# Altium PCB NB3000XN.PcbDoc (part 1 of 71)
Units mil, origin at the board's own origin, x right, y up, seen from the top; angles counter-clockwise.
Board outline 9527.56 x 6929.77 mil, 6 copper layers (Top Layer, GND+SHIELD, MidLayer1, MidLayer2, P2 - 3V3+5V0, Bottom Layer), stack 62.375 mil thick; 832 components, 1027 nets, 4655 pads, 4981 vias.
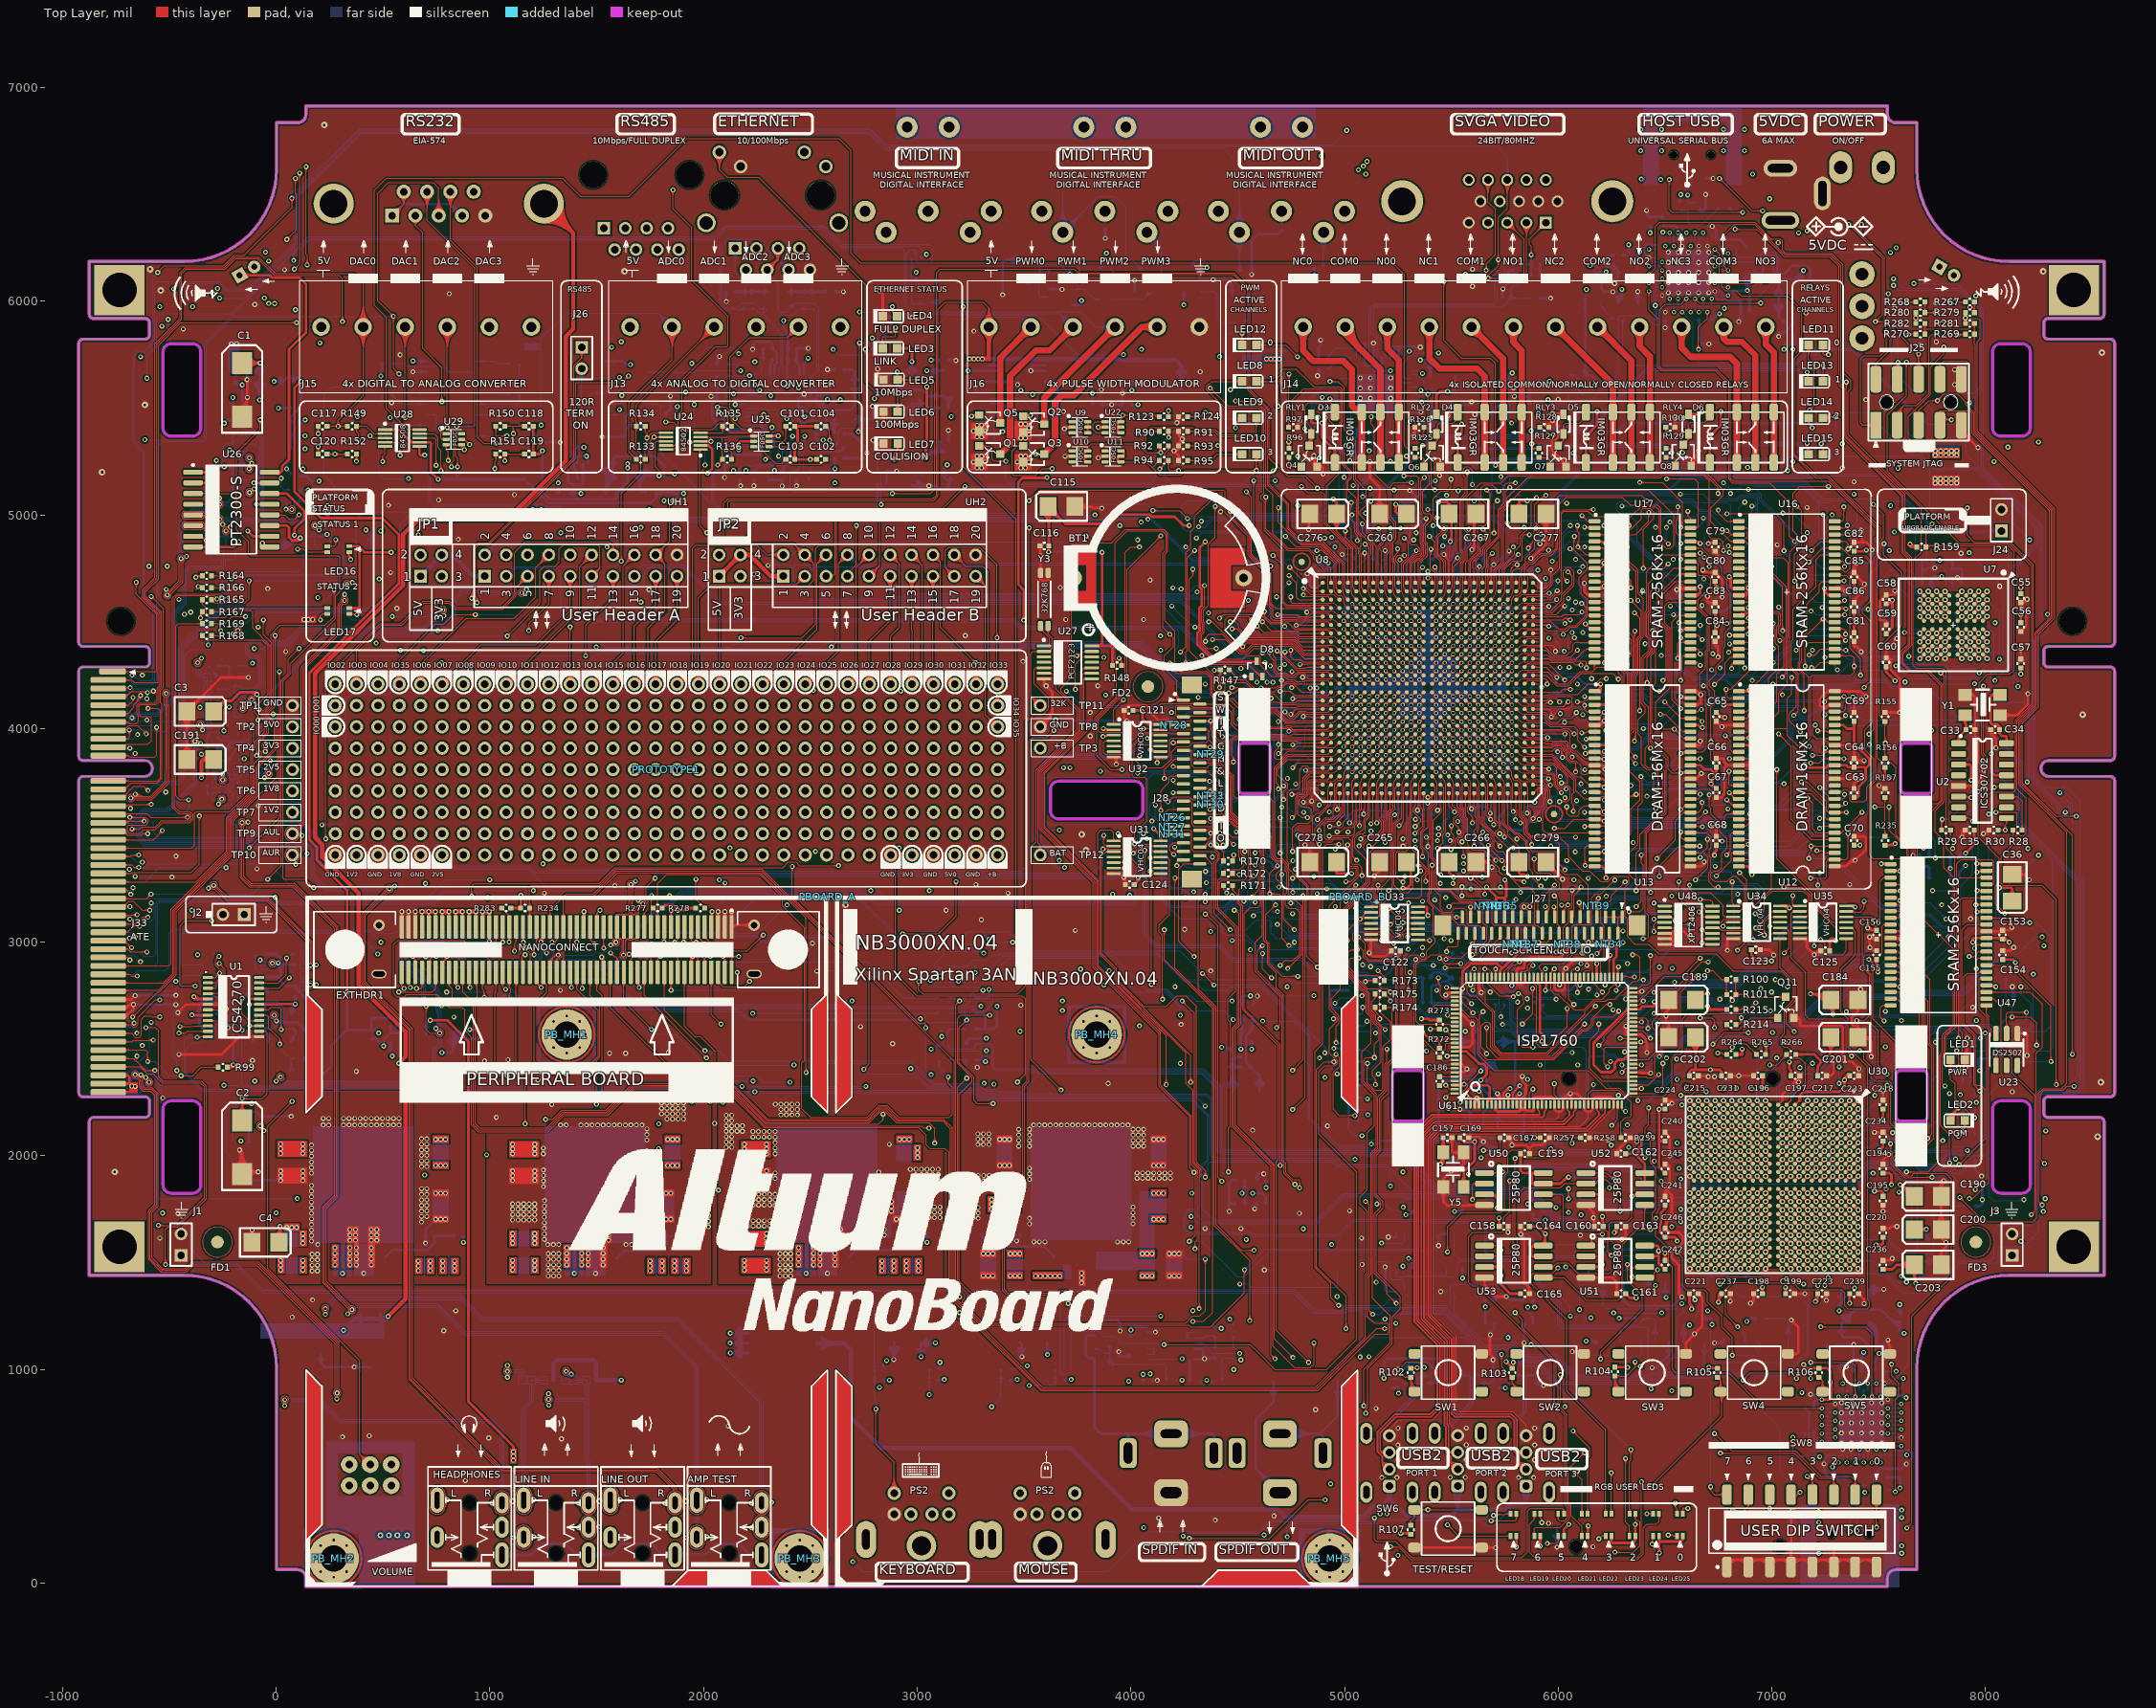
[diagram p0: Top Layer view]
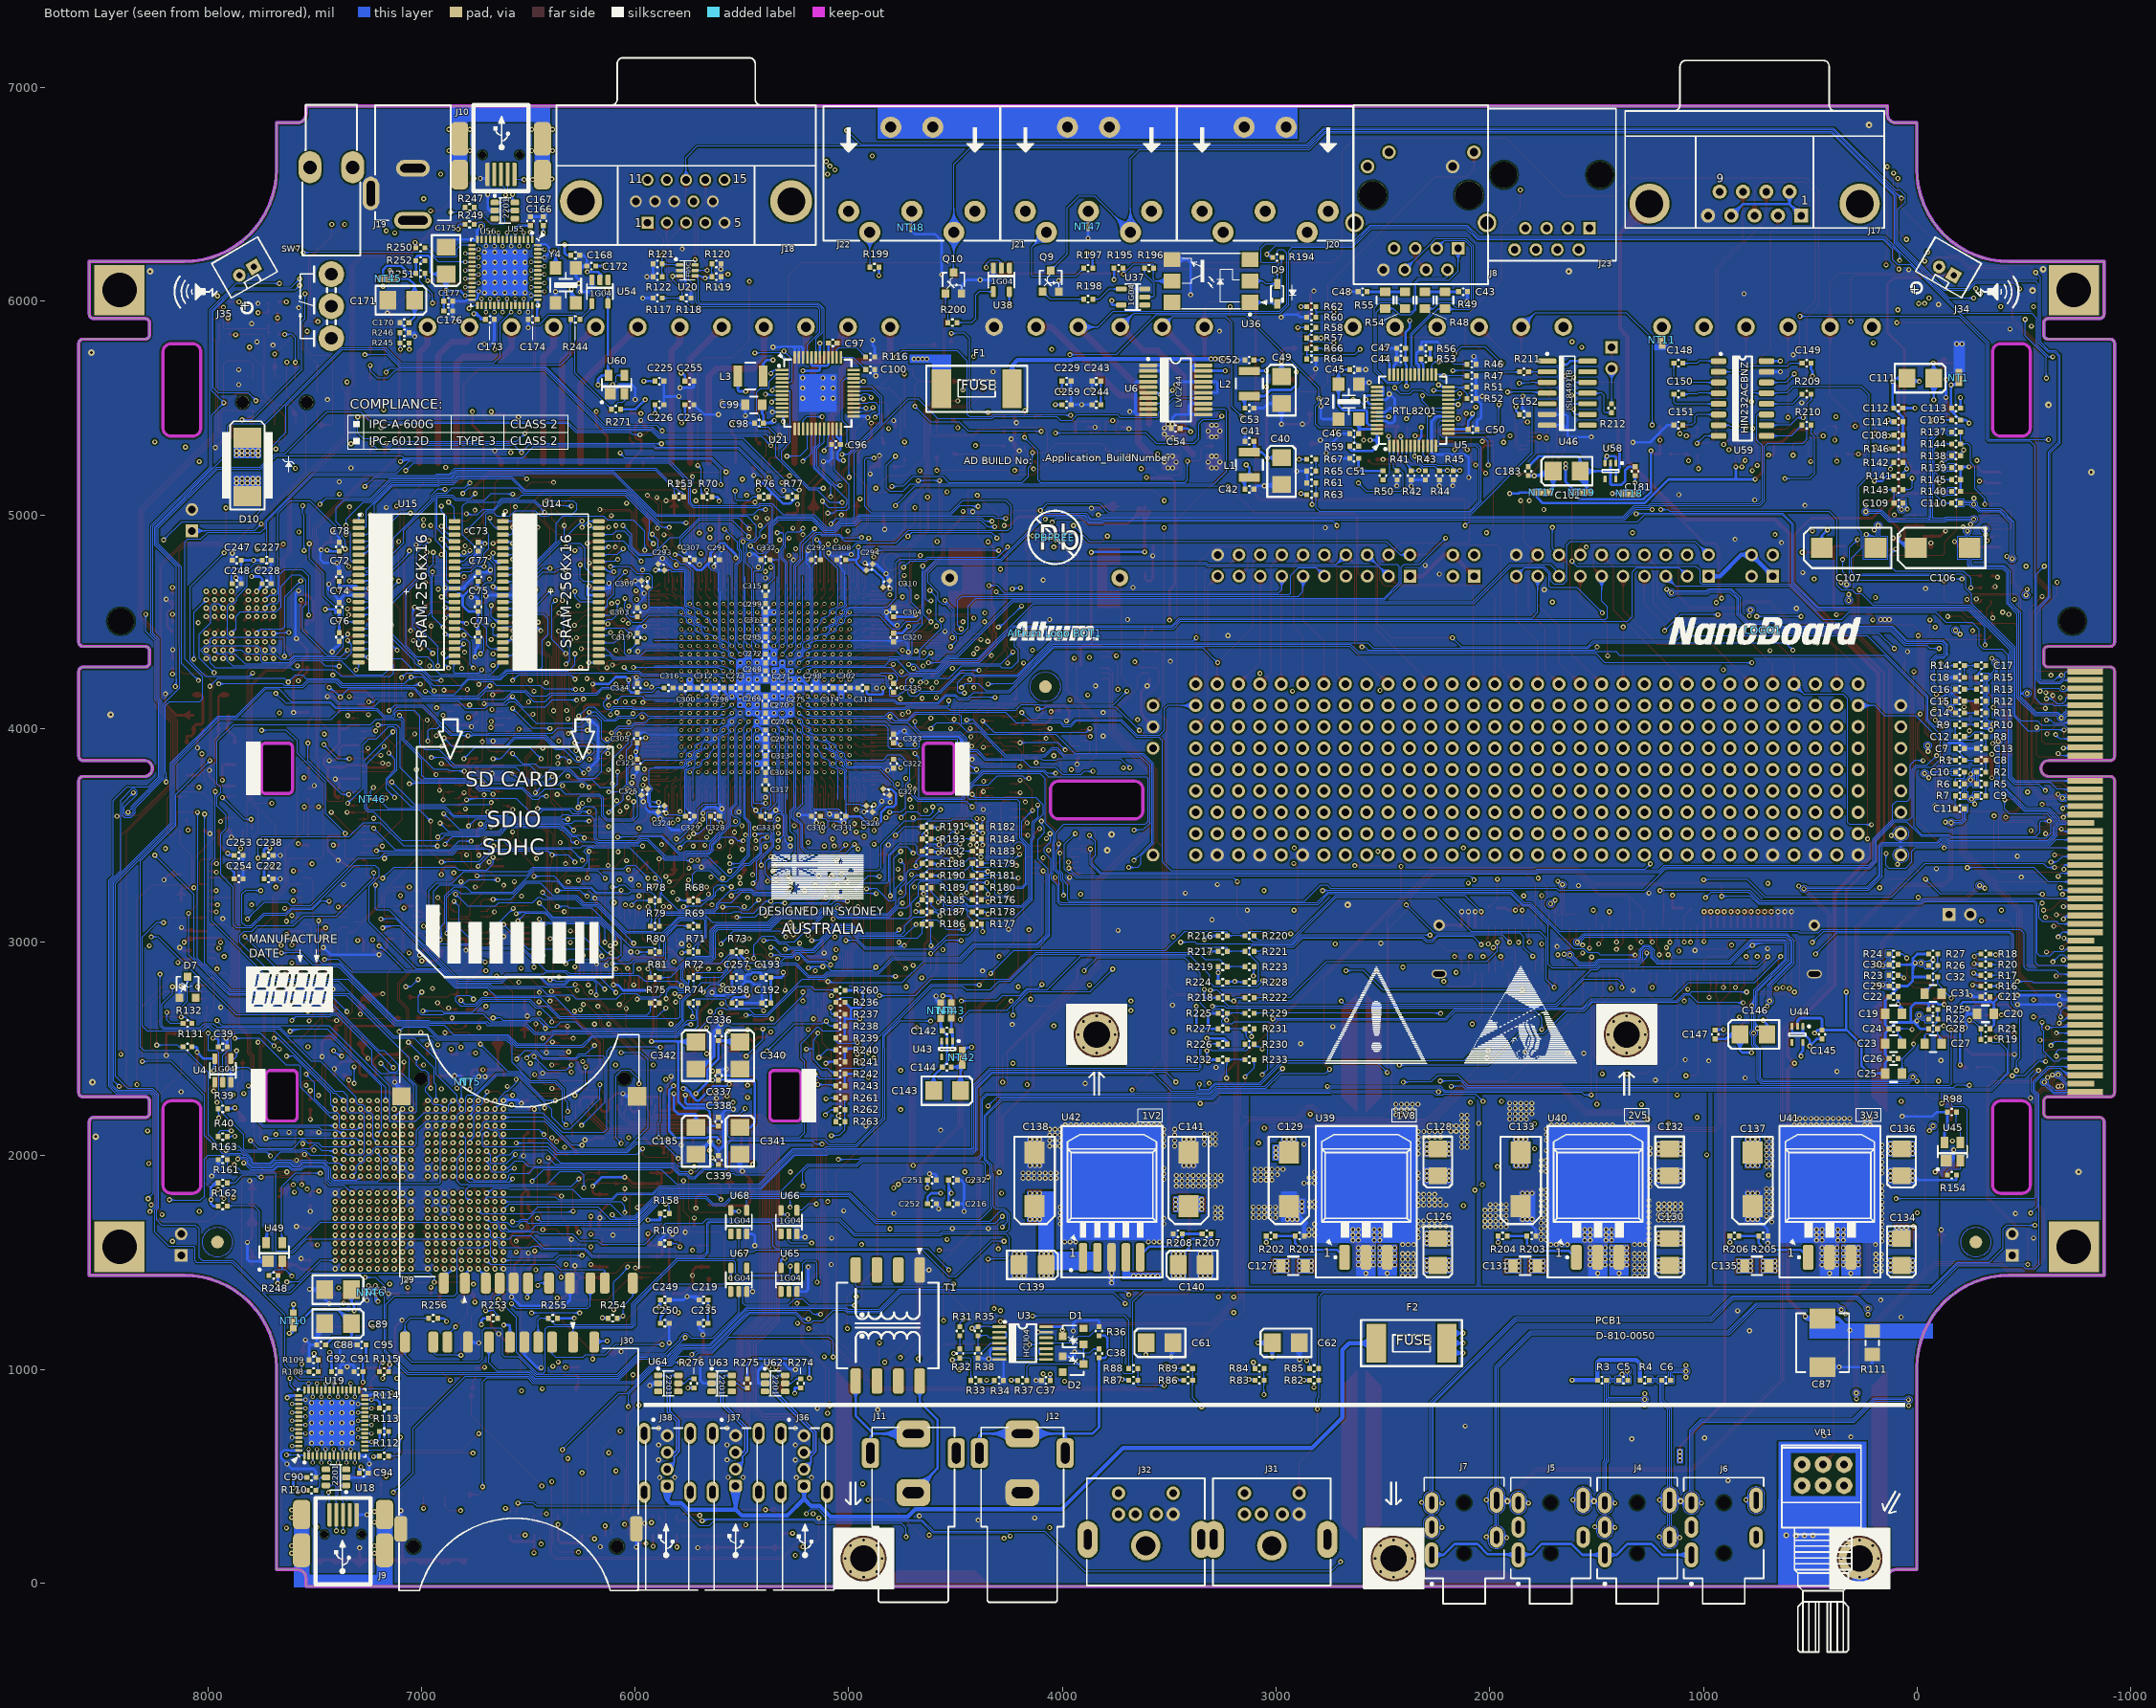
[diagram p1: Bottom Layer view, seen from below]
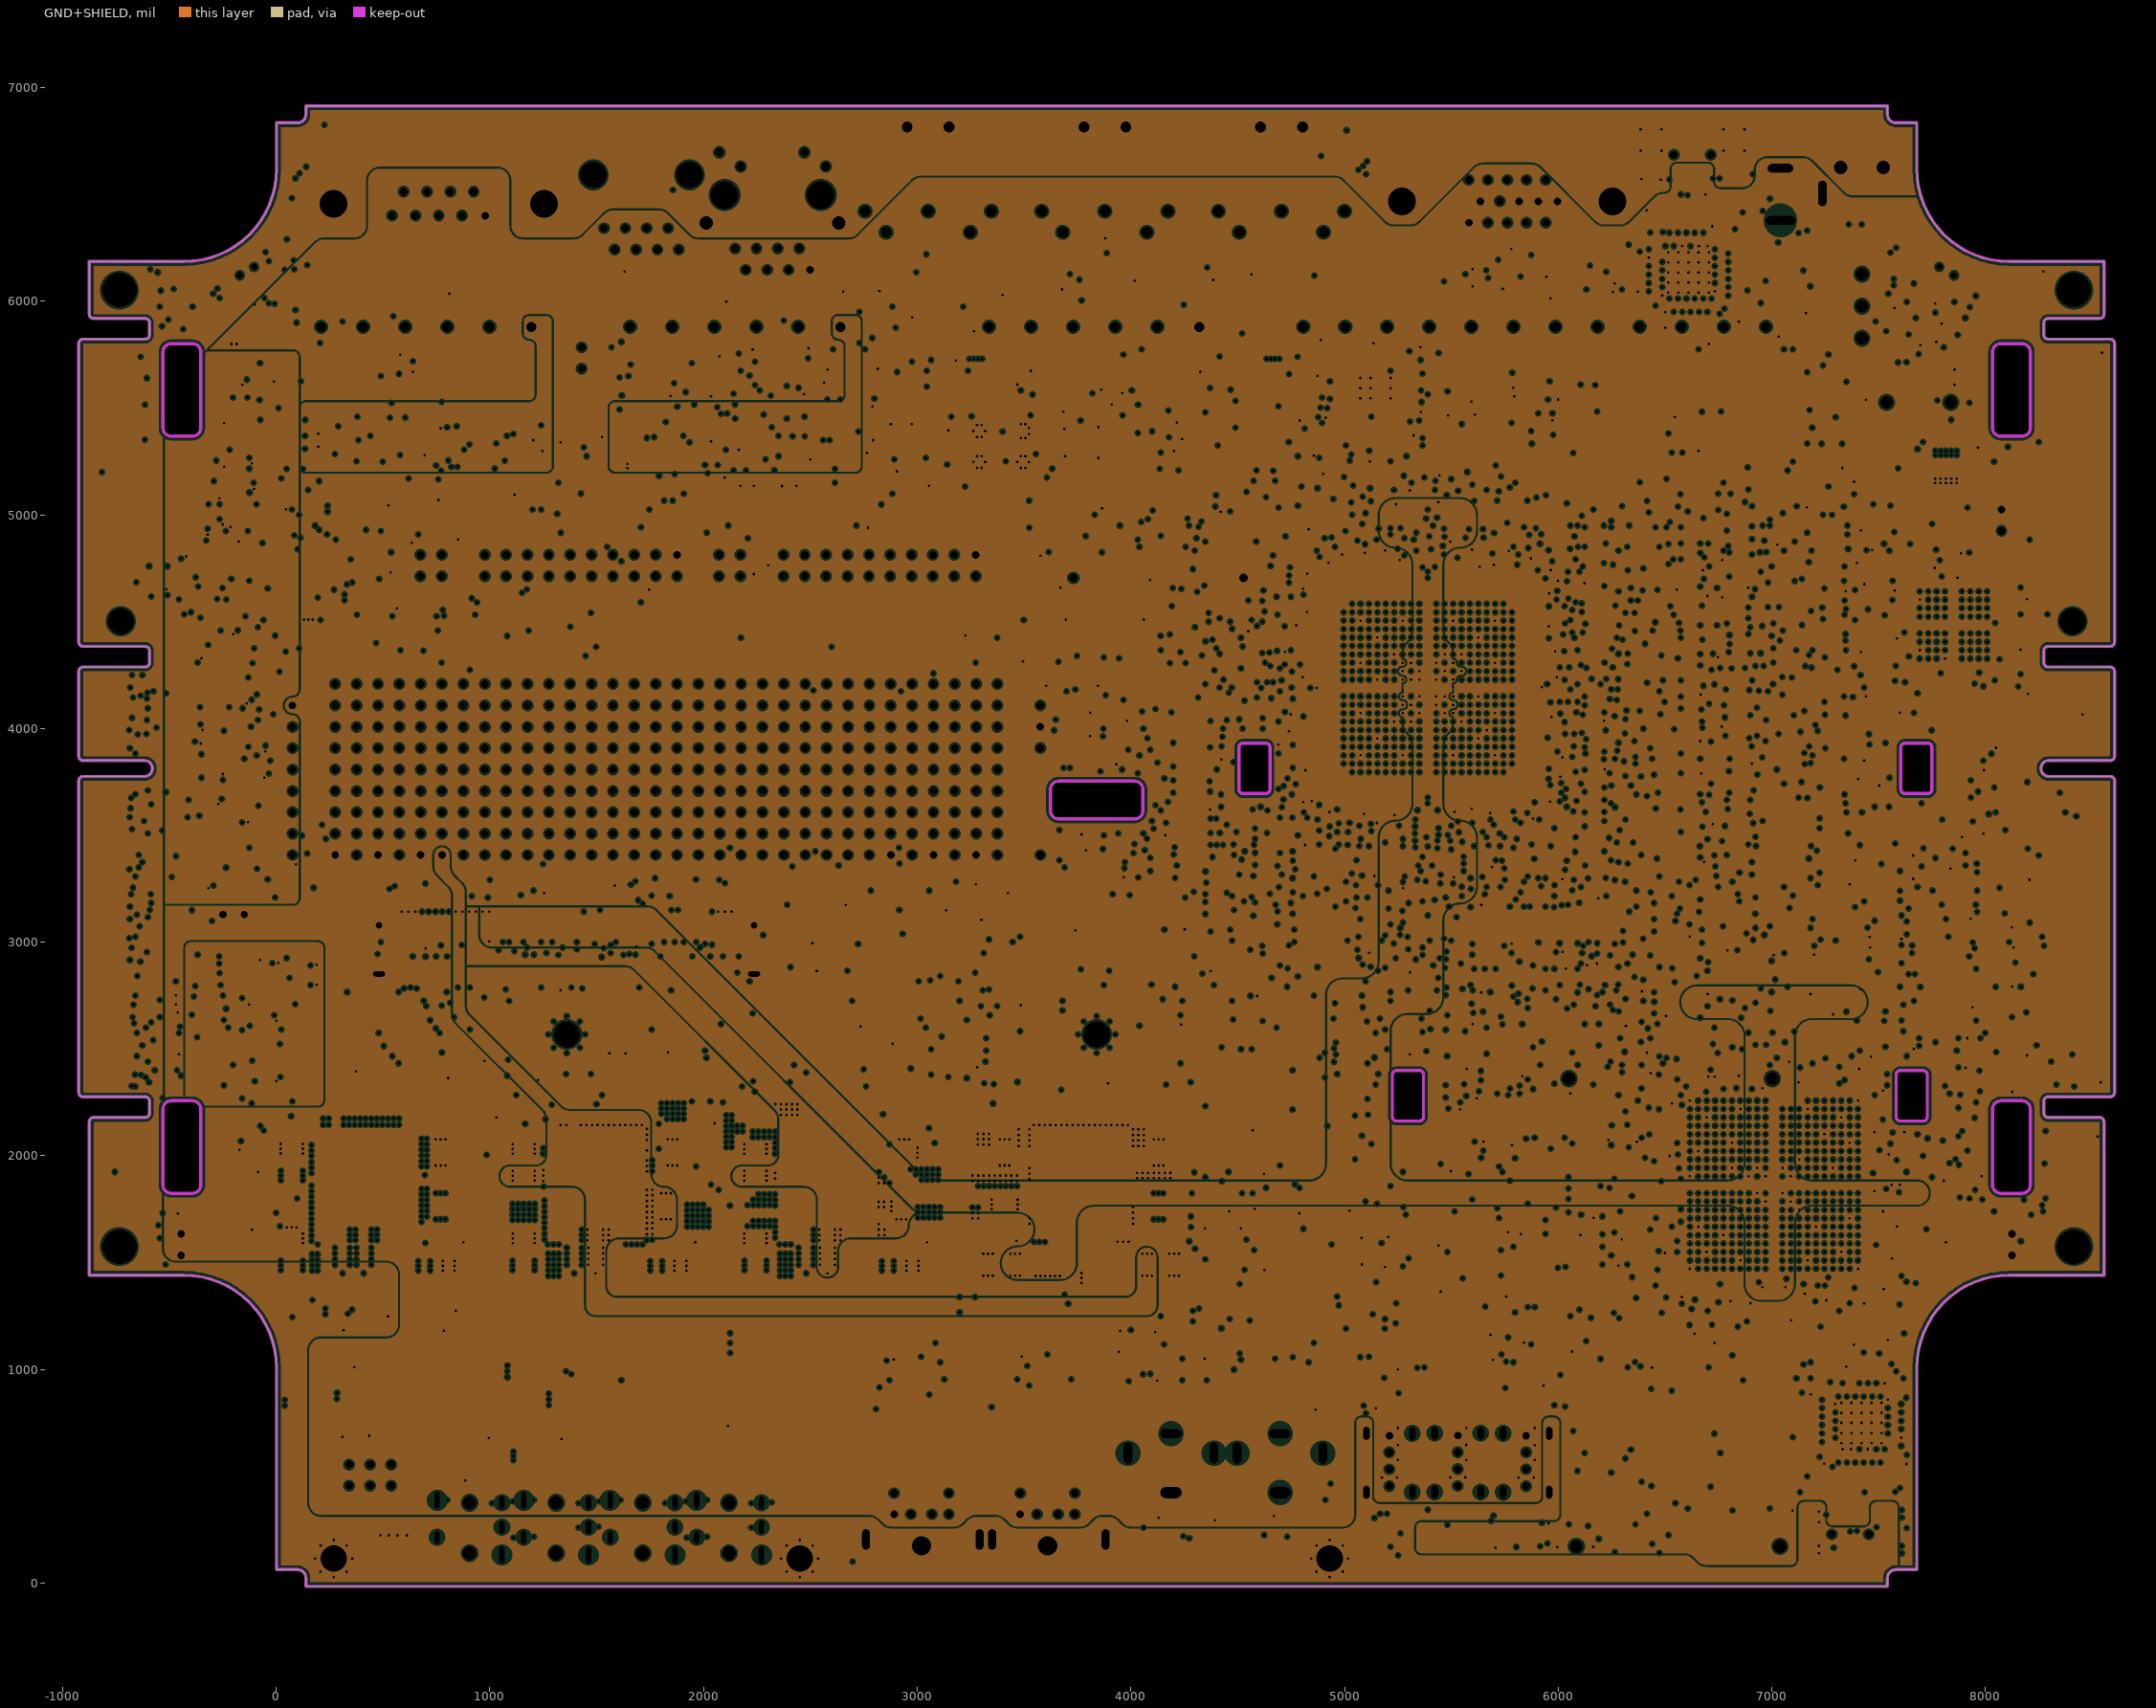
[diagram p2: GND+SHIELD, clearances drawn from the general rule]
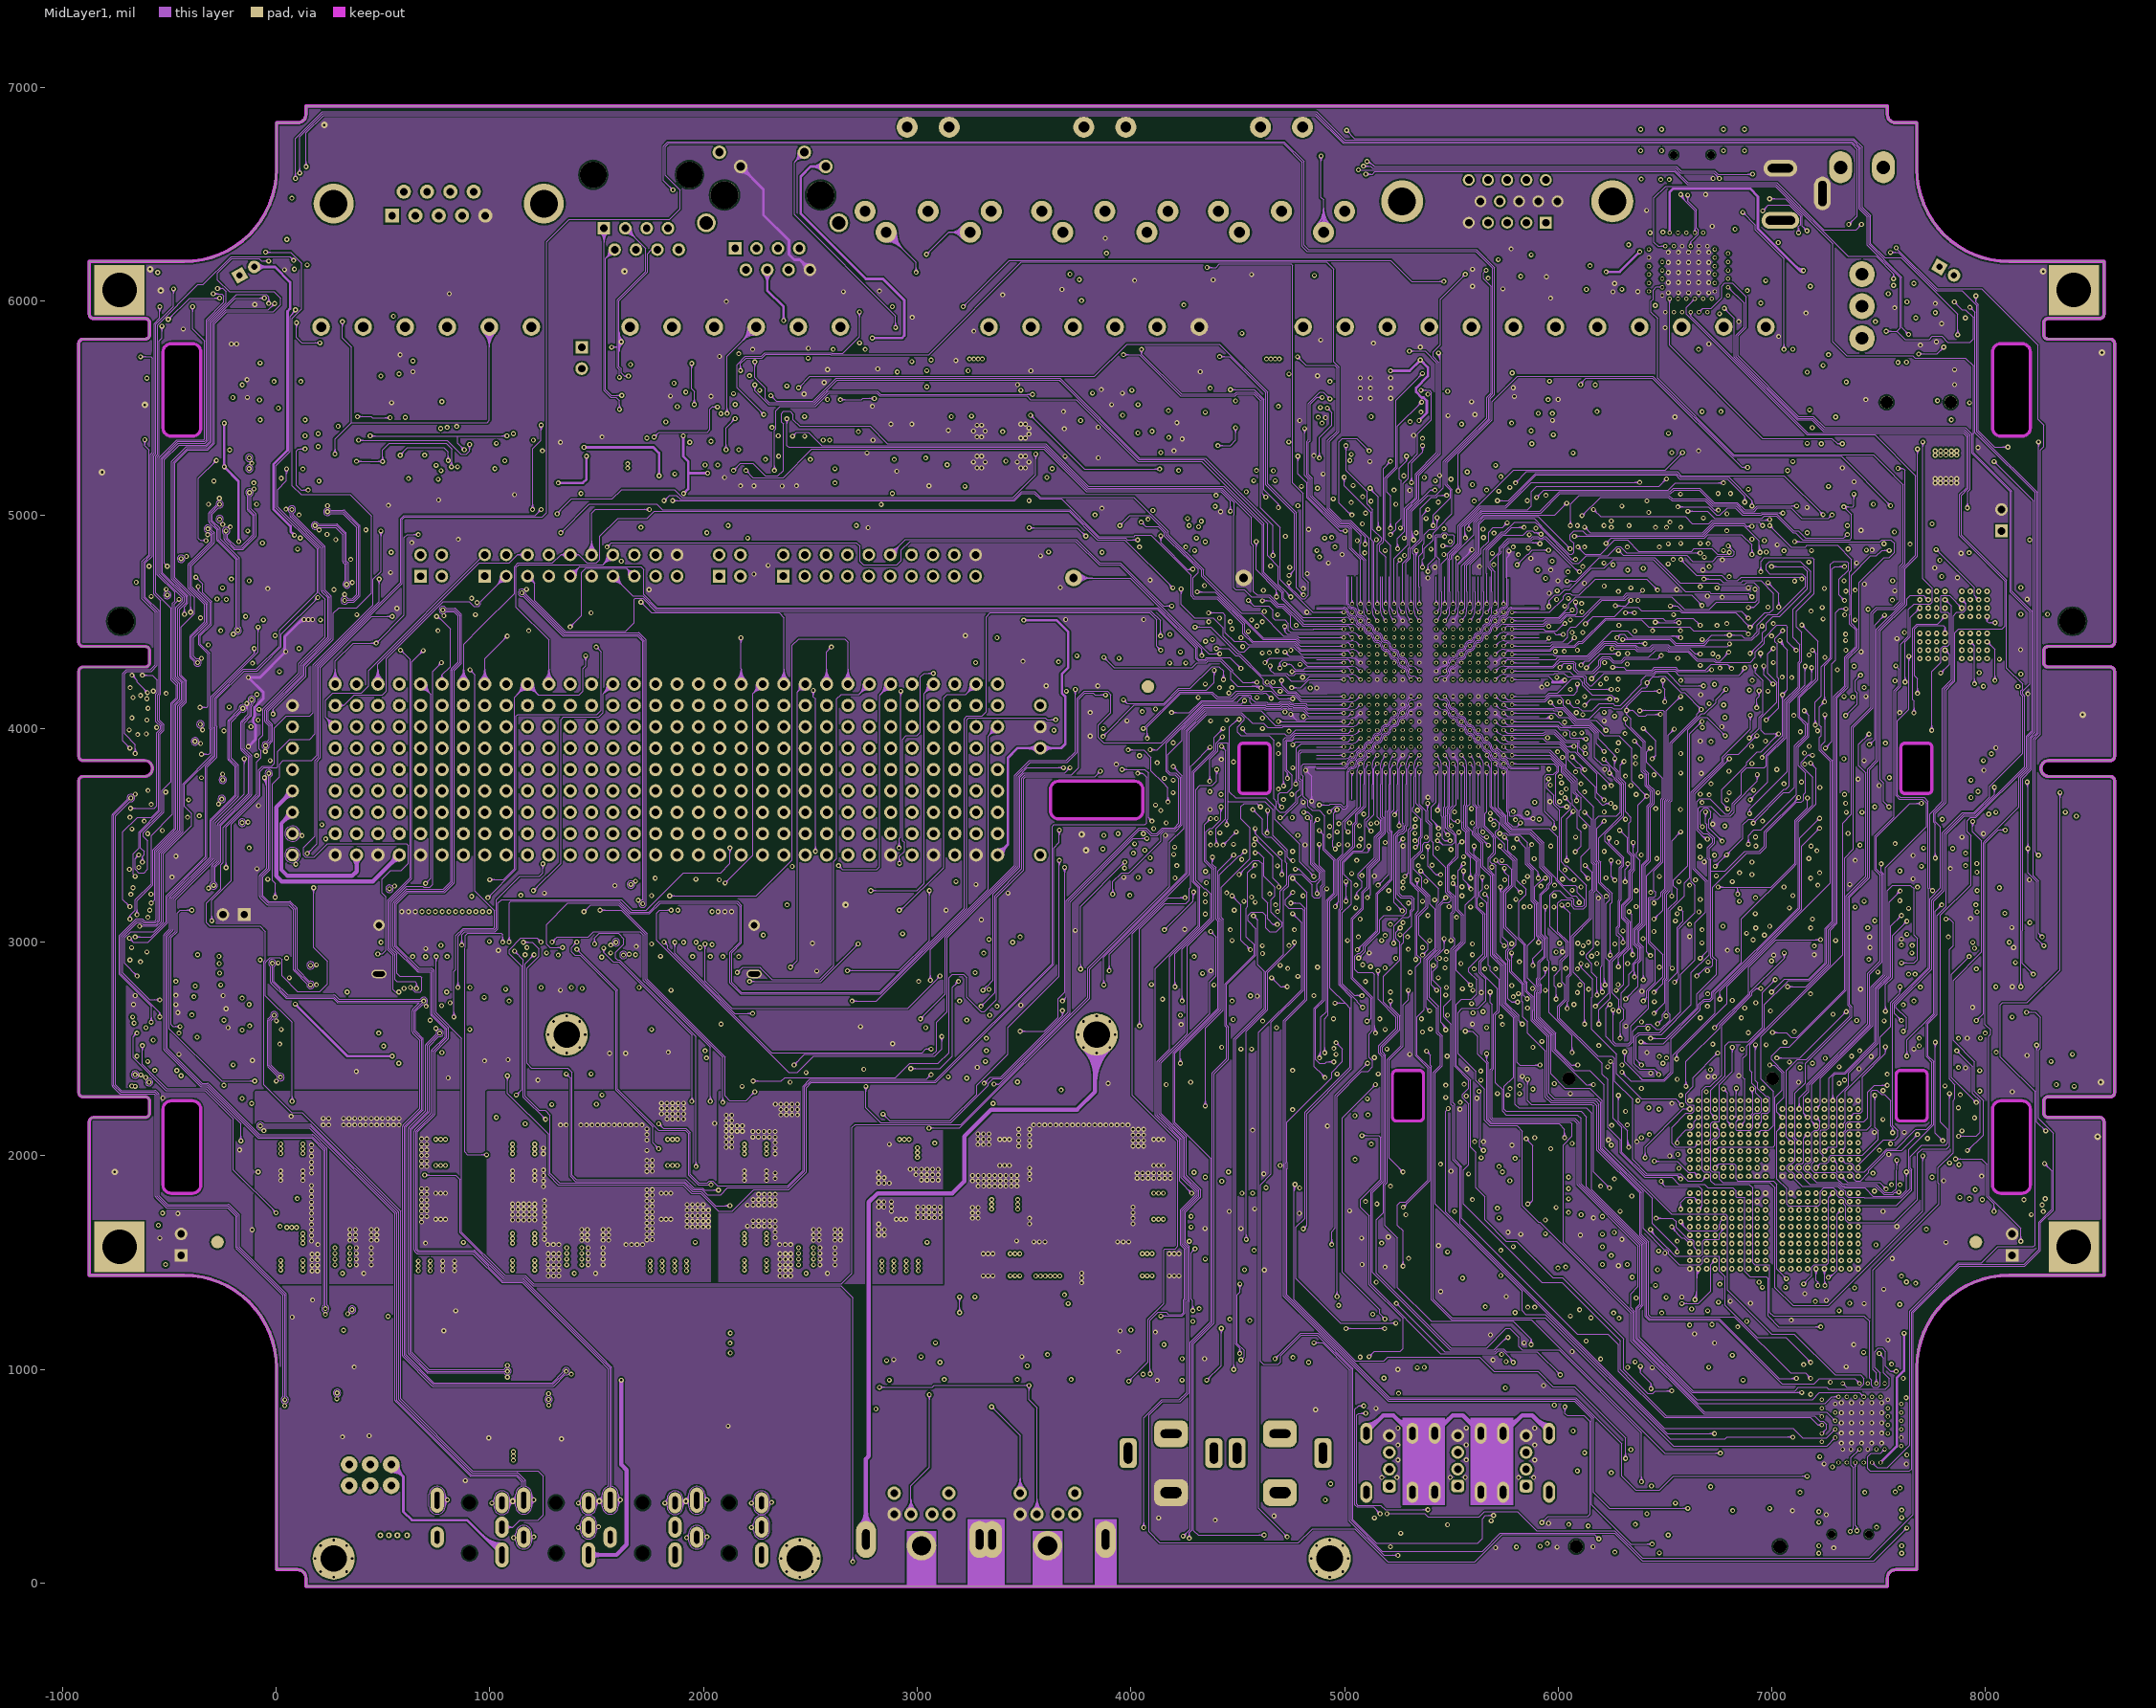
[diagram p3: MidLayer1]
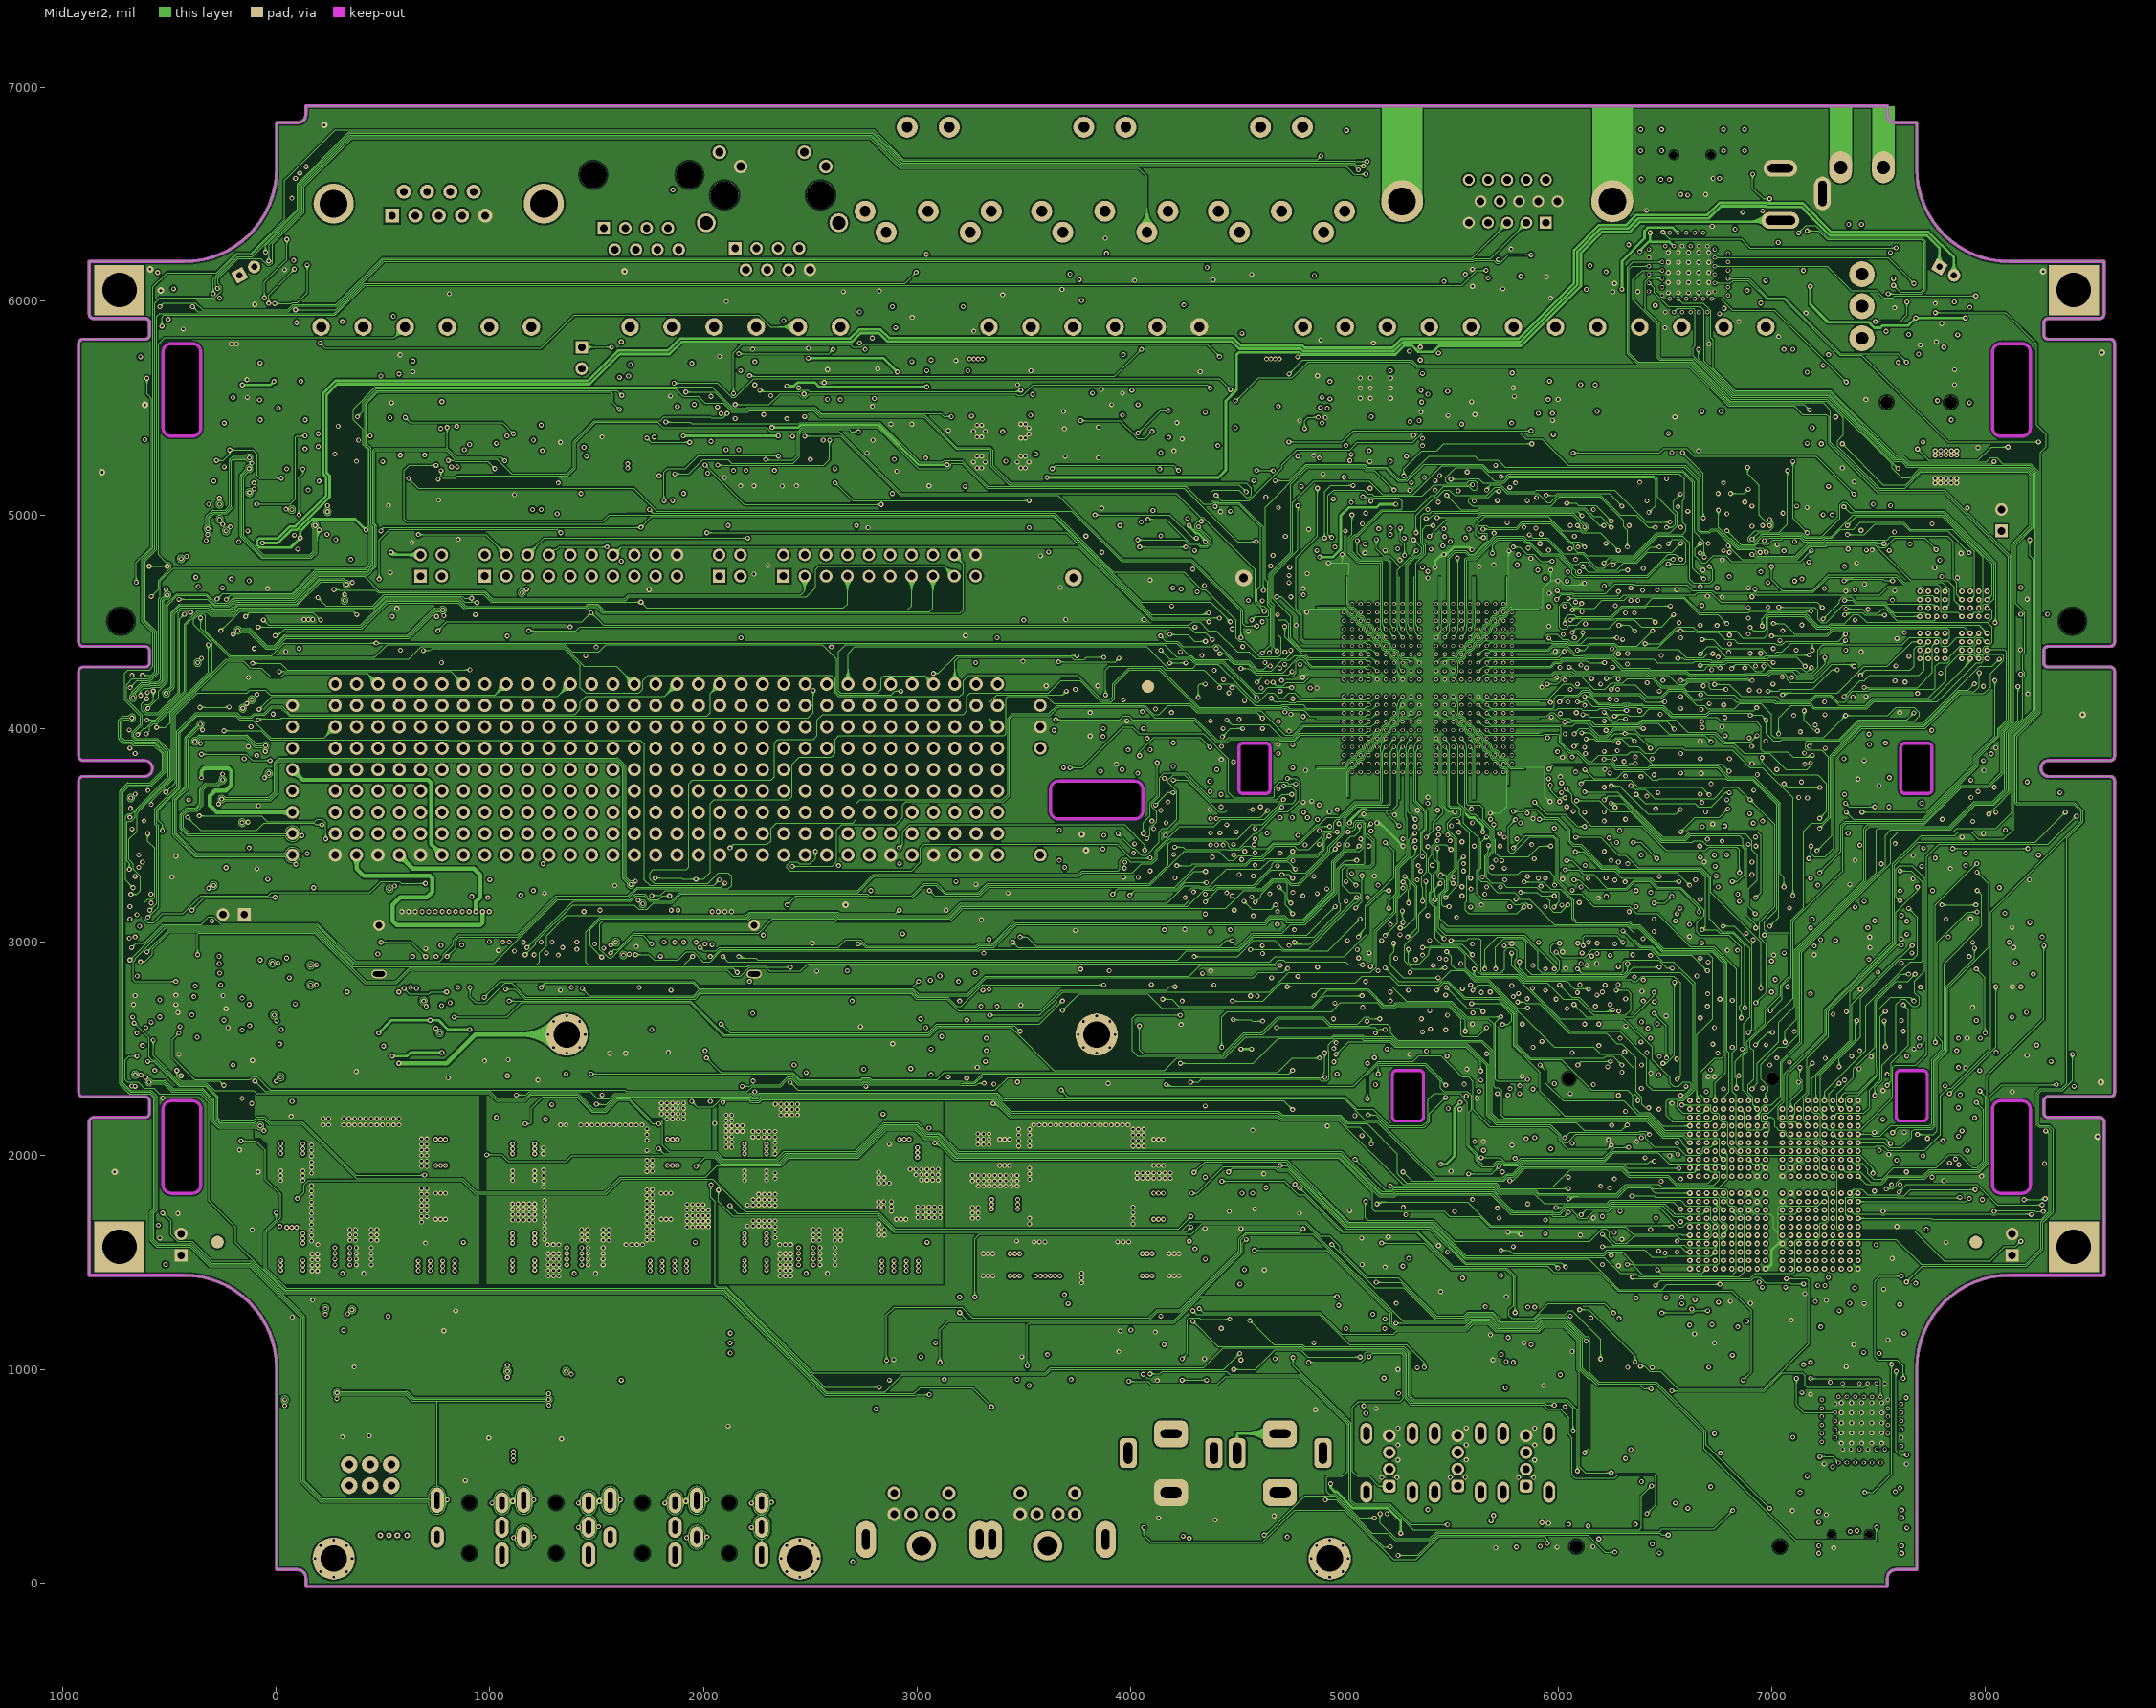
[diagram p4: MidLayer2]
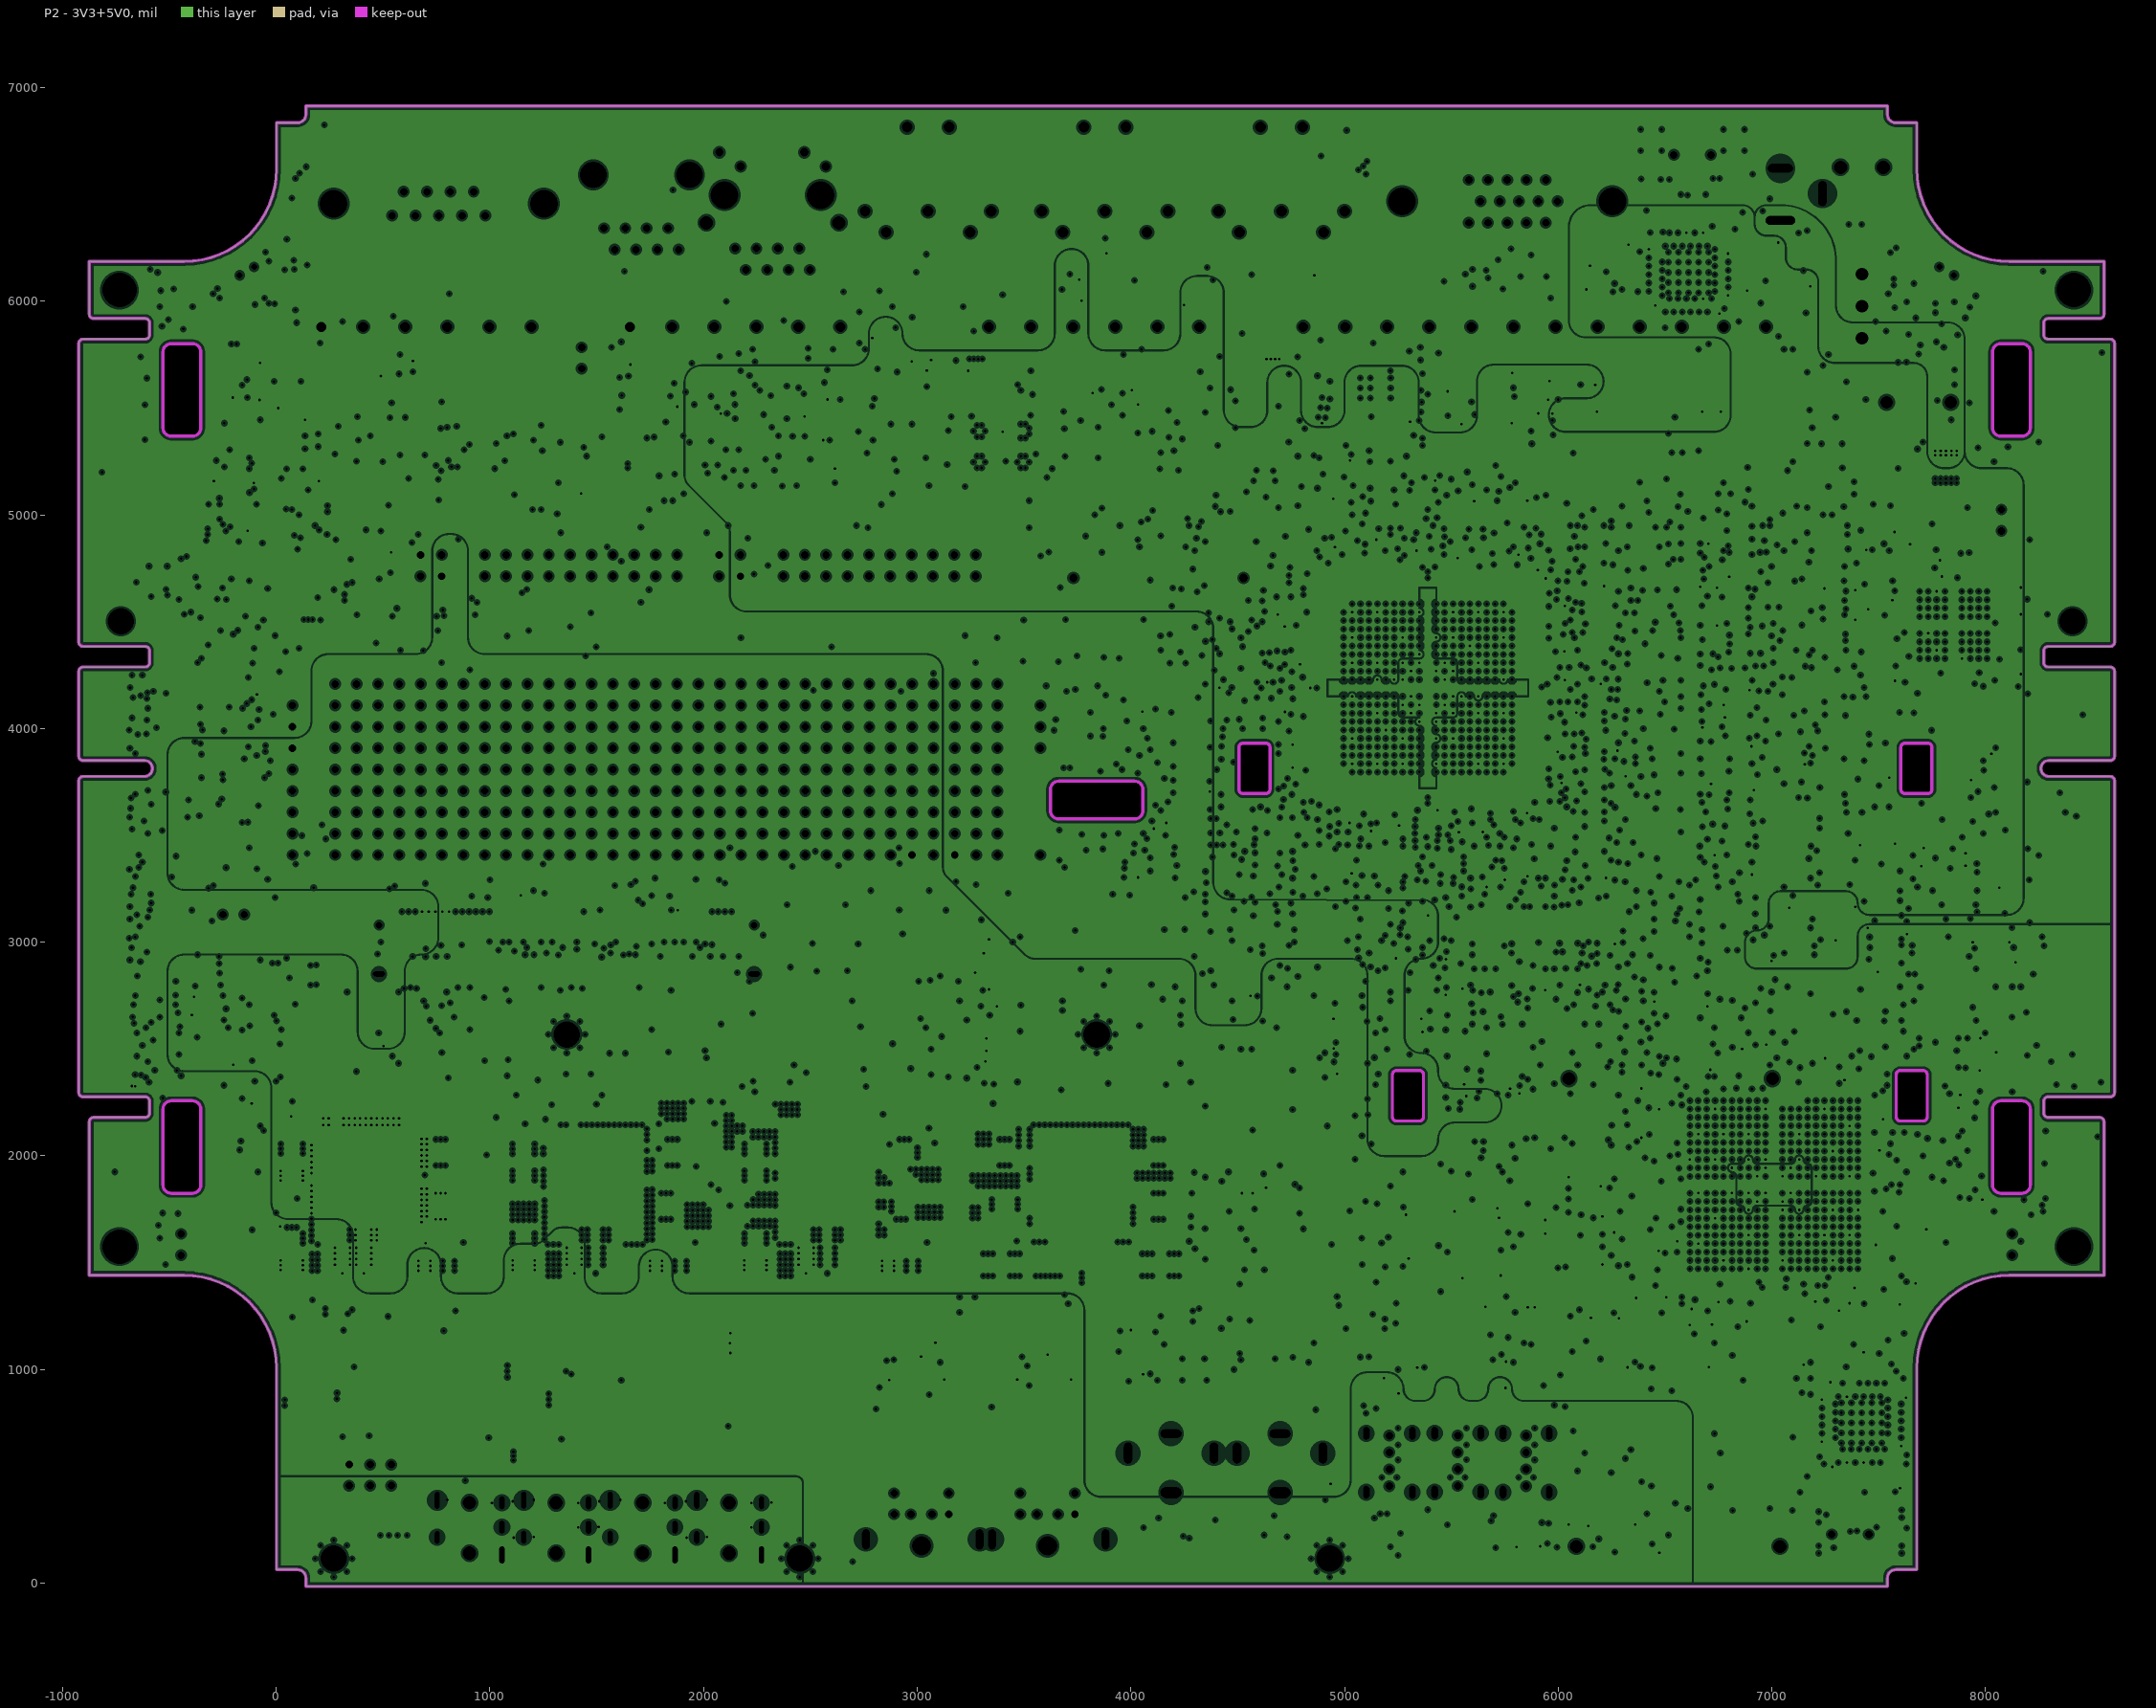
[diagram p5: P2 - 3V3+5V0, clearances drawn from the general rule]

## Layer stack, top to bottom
Top Layer: signal copper 1.4
Dielectric: core 7.874, FR-4, Dk 4.8
GND+SHIELD: plane copper 1.4173, net (Multiple Nets)
Dielectric: prepreg 12.9921, FR-4, Dk 4.8
MidLayer1: signal copper 1.4
Dielectric: core 7.874, FR-4, Dk 4.8
MidLayer2: signal copper 1.4
Dielectric: prepreg 12.6, FR-4, Dk 4.8
P2 - 3V3+5V0: plane copper 1.4173, net (Multiple Nets)
Dielectric: core 12.6, FR-4, Dk 4.8
Bottom Layer: signal copper 1.4

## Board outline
369 vertices, not listed, extent -923.8,-15.55 8603.76,6914.22
cut-out: 8170.69,2257.89 8179.45,2256.91 8187.77,2254 8195.24,2249.3 8201.47,2243.07 8206.16,2235.6 8209.07,2227.28 8210.06,2218.52 8210.06,1864.15 8209.07,1855.39 8206.16,1847.06 8201.47,1839.6 8195.24,1833.36 8187.77,1828.67 8179.45,1825.76 8170.69,1824.77 8072.26,1824.77 8063.5,1825.76 8055.18,1828.67 8047.72,1833.36 8041.48,1839.6 8036.79,1847.06 8033.88,1855.39 8032.89,1864.15 8032.89,2218.52 8033.88,2227.28 8036.79,2235.6 8041.48,2243.07 8047.72,2249.3 8055.18,2254 8063.5,2256.91 8072.26,2257.89
cut-out: 7707.86,2163.13 7601.56,2163.13 7597.18,2163.62 7593.02,2165.08 7589.29,2167.42 7586.17,2170.54 7583.83,2174.27 7582.37,2178.43 7581.87,2182.81 7581.87,2379.69 7582.37,2384.07 7583.83,2388.23 7586.17,2391.96 7589.29,2395.08 7593.02,2397.42 7597.18,2398.88 7601.56,2399.37 7707.86,2399.37 7712.24,2398.88 7716.4,2397.42 7720.13,2395.08 7723.25,2391.96 7725.6,2388.23 7727.05,2384.07 7727.54,2379.69 7727.54,2182.81 7727.05,2178.43 7725.6,2174.27 7723.25,2170.54 7720.13,2167.42 7716.4,2165.08 7712.24,2163.62
cut-out: 3623.45,3714.76 3624.43,3723.52 3627.34,3731.84 3632.03,3739.31 3638.27,3745.54 3645.73,3750.24 3654.05,3753.15 3662.81,3754.13 4017.15,3754.13 4025.91,3753.15 4034.23,3750.24 4041.69,3745.54 4047.93,3739.31 4052.62,3731.84 4055.53,3723.52 4056.52,3714.76 4056.52,3616.32 4055.53,3607.56 4052.62,3599.24 4047.93,3591.77 4041.69,3585.54 4034.23,3580.85 4025.91,3577.94 4017.15,3576.95 3662.81,3576.95 3654.05,3577.94 3645.73,3580.85 3638.27,3585.54 3632.03,3591.77 3627.34,3599.24 3624.43,3607.56 3623.45,3616.32
cut-out: -490.73,5368.5 -499.49,5369.49 -507.81,5372.4 -515.27,5377.09 -521.51,5383.32 -526.2,5390.79 -529.11,5399.11 -530.1,5407.88 -530.1,5762.25 -529.11,5771.01 -526.2,5779.33 -521.51,5786.8 -515.27,5793.03 -507.81,5797.72 -499.49,5800.64 -490.73,5801.62 -392.3,5801.62 -383.54,5800.64 -375.22,5797.72 -367.76,5793.03 -361.52,5786.8 -356.83,5779.33 -353.92,5771.01 -352.93,5762.25 -352.93,5407.88 -353.92,5399.11 -356.83,5390.79 -361.52,5383.32 -367.76,5377.09 -375.22,5372.4 -383.54,5369.49 -392.3,5368.5
cut-out: 8210.06,5762.25 8210.06,5407.88 8209.07,5399.11 8206.16,5390.79 8201.47,5383.32 8195.24,5377.09 8187.77,5372.4 8179.45,5369.49 8170.69,5368.5 8072.26,5368.5 8063.5,5369.49 8055.18,5372.4 8047.72,5377.09 8041.48,5383.32 8036.79,5390.79 8033.88,5399.11 8032.89,5407.88 8032.89,5762.25 8033.88,5771.01 8036.79,5779.33 8041.48,5786.8 8047.72,5793.03 8055.18,5797.72 8063.5,5800.64 8072.26,5801.62 8170.69,5801.62 8179.45,5800.64 8187.77,5797.72 8195.24,5793.03 8201.47,5786.8 8206.16,5779.33 8209.07,5771.01
cut-out: -530.1,1864.15 -530.1,2218.52 -529.11,2227.28 -526.2,2235.6 -521.51,2243.07 -515.27,2249.3 -507.81,2253.99 -499.49,2256.91 -490.73,2257.89 -392.3,2257.89 -383.54,2256.91 -375.22,2253.99 -367.76,2249.3 -361.52,2243.07 -356.83,2235.6 -353.92,2227.28 -352.93,2218.52 -352.93,1864.15 -353.92,1855.38 -356.83,1847.06 -361.52,1839.6 -367.76,1833.36 -375.22,1828.67 -383.54,1825.76 -392.3,1824.77 -490.73,1824.77 -499.49,1825.76 -507.81,1828.67 -515.27,1833.36 -521.51,1839.6 -526.2,1847.06 -529.11,1855.38
cut-out: 5243.76,2399.37 5350.06,2399.37 5354.43,2398.88 5358.6,2397.42 5362.33,2395.08 5365.45,2391.96 5367.79,2388.23 5369.25,2384.07 5369.74,2379.69 5369.74,2182.81 5369.25,2178.43 5367.79,2174.27 5365.45,2170.54 5362.33,2167.42 5358.6,2165.08 5354.43,2163.62 5350.06,2163.13 5243.76,2163.13 5239.37,2163.62 5235.21,2165.08 5231.48,2167.42 5228.37,2170.54 5226.02,2174.27 5224.57,2178.43 5224.07,2182.81 5224.07,2379.69 5224.57,2384.07 5226.02,2388.23 5228.37,2391.96 5231.48,2395.08 5235.21,2397.42 5239.37,2398.88
cut-out: 4505.53,3912.08 4506.03,3916.47 4507.48,3920.63 4509.83,3924.36 4512.95,3927.48 4516.68,3929.82 4520.84,3931.28 4525.22,3931.77 4631.52,3931.77 4635.9,3931.28 4640.06,3929.82 4643.79,3927.48 4646.91,3924.36 4649.25,3920.63 4650.71,3916.47 4651.21,3912.08 4651.21,3715.21 4650.71,3710.83 4649.25,3706.67 4646.91,3702.94 4643.79,3699.82 4640.06,3697.47 4635.9,3696.02 4631.52,3695.52 4525.22,3695.52 4520.84,3696.02 4516.68,3697.47 4512.95,3699.82 4509.83,3702.94 4507.48,3706.67 4506.03,3710.83 4505.53,3715.21
cut-out: 7623.64,3931.77 7729.94,3931.77 7734.32,3931.28 7738.48,3929.82 7742.21,3927.48 7745.33,3924.36 7747.67,3920.63 7749.13,3916.47 7749.62,3912.08 7749.62,3715.21 7749.13,3710.83 7747.67,3706.67 7745.33,3702.94 7742.21,3699.82 7738.48,3697.47 7734.32,3696.02 7729.94,3695.52 7623.64,3695.52 7619.26,3696.02 7615.1,3697.47 7611.37,3699.82 7608.25,3702.94 7605.9,3706.67 7604.45,3710.83 7603.95,3715.21 7603.95,3912.08 7604.45,3916.47 7605.9,3920.63 7608.25,3924.36 7611.37,3927.48 7615.1,3929.82 7619.26,3931.28

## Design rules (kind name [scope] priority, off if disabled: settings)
Clearance Polygons [InPolygon] p1: gap=8
Clearance "General Clearance" [All] p2: gap=4
ComponentClearance "Small SMD" [HasFootprint('RESC1005-STAR') or Hasfootprint('CAPC3528-STAR') or Hasfootprint('0603LED')   or Hasfootprint('CAPC1005-STAR')] p1: gap=-39.37 collisioncheckmode=3 verticalgap=10 showdistances=FALSE
ComponentClearance "Peripheral and Daughter" [InComponentClass('Plug In Boards') vs InComponentClass('Plug In Board Headers') or HasFootprint('STANDOFF_SOLDER_3MM')] p2: gap=0 collisioncheckmode=3 verticalgap=0 showdistances=FALSE
ComponentClearance "Net Ties" [IsNetTieComponent] p3: gap=-39.37 collisioncheckmode=3 verticalgap=-39.37 showdistances=FALSE
ComponentClearance [All] p4: gap=7.87 collisioncheckmode=3 verticalgap=39.37 showdistances=FALSE
DiffPairsRouting DiffPair_DiffPairsRouting [All] p1: maxlimit=12.6 minlimit=11.02 mostfreqgap=11.81 maxuncoupledlength=500
DiffPairsRouting PairRoute [All] p2: maxlimit=5.91 minlimit=5 mostfreqgap=5 maxuncoupledlength=393.7
FabricationTestPointUsage TestPointUsage [All] p1 off: valid=0 allowmultiple=FALSE
FabricationTestpoint Testpoint [All] p1 off: side=3 testpointundercomponent=TRUE minsize=40 maxsize=100 preferedsize=60 minholesize=0 maxholesize=40 preferedholesize=32 testpointgrid=1 allowsidetop=TRUE allowsidebottom=TRUE usegrid=TRUE gridtolerance=0.01
FanoutControl Fanout_BGA [All] p1: bgadir=Out bgaviamode=Centered fanoutstyle=BGA fanoutdirection=OutOnly viagrid=1 // Fanout_BGA (Default Rule)
FanoutControl Fanout_Default [All] p5: bgadir=Out bgaviamode=Centered fanoutstyle=BGA fanoutdirection=Alternating viagrid=1 // Fanout_Default (Default Rule)
HoleSize [IsPad And (holesize <> 0)] p1: absolutevalues=TRUE maxlimit=204.72 minlimit=11.81 maxpercent=80.000 minpercent=20.000
MatchedLengths DiffPair_MatchedLengths [(IsDifferentialPair And (Name = 'USB_DP'))] p1: tolerance=393.7 checknetsindiffpair=TRUE checkdiffpairvsdiffpair=TRUE checkothers=TRUE
MatchedLengths DiffPair_MatchedLengths_1 [(IsDifferentialPair And (Name = 'DIFF_RX1'))] p2: tolerance=1000 checknetsindiffpair=TRUE checkdiffpairvsdiffpair=TRUE checkothers=TRUE
MinimumAnnularRing [PadIsPlated And (Name <> 'Y1_RT')] p1 off: minimumring=7.87
PlaneClearance [All] p1: clearance=10
PlaneConnect [All] p1: planeconnectstyle=Direct reliefexpansion=20 reliefentries=4 reliefconductorwidth=10 reliefairgap=10
PolygonConnect [All] p1: connectstyle=Direct reliefconductorwidth=10 reliefentries=4 polygonreliefangle="90 Angle"
RoutingVias [All] p1: holewidth=11.81 width=23.62 viastyle="Through Hole" minholewidth=11.81 minwidth=23 maxholewidth=39.37 maxwidth=78.74
ShortCircuit ShortCircuit_1 [Net = 'No Net' vs Net = 'No Net'] p1: allowed=TRUE
ShortCircuit [All] p2: allowed=FALSE
SilkscreenOverComponentPads [All] p1: minsilkscreentomaskgap=10
SolderMaskExpansion SolderMaskExpansion_Vias [IsVia] p1: expansion=-30
SolderMaskExpansion [All] p2: expansion=1.5
Width [All] p1: maxlimit=157.48 minlimit=4 preferedwidth=5
17 further rules are at their usual default settings.

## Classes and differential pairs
channel class FPGA_Bypass_3V3: DECOUPLING_CAPS_3V31 DECOUPLING_CAPS_3V32
channel class FPGA_Bypass_1V2: DECOUPLING_CAPS_1V21 DECOUPLING_CAPS_1V22
channel class USB_CY7C68001-56LFC: DBUSB_TXRX1 DBUSB_TXRX2
channel class PSU_ZXCL330_3V3: PSU_A3V3_ADC1 PSU_A3V3_ADC2 PSU_A3V3_CODEC PSU_A3V3_DAC
channel class PSU_1084_ADJ: PSU_1V8 PSU_2V5 PSU_3V3
channel class LED_RGB_SMDx2: HOST_LED U_LED_01 U_LED_23 U_LED_45 U_LED_67
channel class CON_SD_KSDC012551: CON_DBSD1 CON_DBSD2
channel class SRAM_256Kx16_TSOP44: U_SRAM1 U_SRAM2
channel class RELAY_SMT_5V_IM03GR: U_RELAY0 U_RELAY1 U_RELAY2 U_RELAY3
pad class "GND Net Link Pads": NT1-2 NT2-1 NT2-2 U13-11
pad class Connector_Slot_Pads: J6-1 J6-3 J7-1 J7-2 J7-3 U1MIC-6
polygon class HeatsinkPolygons: POWER-BL-1V2 POWER-BL-1V8 POWER-BL-2V5 POWER-BL-3V3 POWER-BL-VCCX POWER-TL-1V2 POWER-TL-1V8 POWER-TL-2V5 POWER-TL-3V3 POWER-TL-VCCX
channel class PC_PS2: KEYBOARD MOUSE
component class StatusLEDS: C39 LED1 LED2 R39 R40 U4
channel class PWRCTRL_RELAY_PWM_28V2A: PWRPWM0 PWRPWM1 PWRPWM2 PWRPWM3
channel class CON_PS2PORT_MINIDIN6F_BLACK: CON_KEYBOARD CON_MOUSE
channel class CON_MINI_USBB_RA_KME04-USBMU03A01-1: CON_DBUSB CON_USB
channel class FLASH_M25PX0_SPI_8Mbit: GOLDEN SYSBOOT
channel class CON_USBA_RA_UPRIGHT: CON_USB1 CON_USB2 CON_USB3
component class ADC: C101 C102 C103 C104 R133 R134 R135 R136 U24 U25
component class AMP_PT2300: C105 C106 C107 C108 C109 C110 C111 C112 C113 C114 R137 R138 R139 R140 R141 R142 R143 R144 R145 R146 U26
component class "ATE INTERFACE": J33
component class AUDIO_AMP: C5 C6 C7 C8 C9 C10 C11 C12 C13 C14 C15 C16 C17 C18 R1 R2 R3 R4 R5 R6 R7 R8 R9 R10 R11 R12 R13 R14 R15 TP9 TP10 VR1
component class CLK_PLL: C33 C34 C35 C36 R28 R29 R30 U2 Y1
component class CODEC_CS4270: C19 C20 C21 C22 C23 C24 C25 C26 C27 C28 C29 C30 C31 C32 R16 R17 R18 R19 R20 R21 R22 R23 R24 R25 R26 R27 U1
component class COM_FLASH: C55 C56 C57 C58 C59 C60 U7
component class COM_SDRAM: C63 C64 C65 C66 C67 C68 C69 C70 U12 U13
component class COM_SRAM: C79 C80 C81 C82 C83 C84 C85 C86 U16 U17
component class COMP_5V0: J19 SW7
component class CON_ADC: J13
component class CON_AUDIO: J4 J5 J6 J7
component class CON_BATT: BT1
component class CON_DAC: J15
component class CON_DBSD1: J29 R253 R254 U65 U66
component class CON_DBSD2: J30 R255 R256 U67 U68
component class CON_DBUSB: J9
component class CON_ETH: J8
component class CON_IO: JP1 JP2 UH1 UH2
component class CON_KEYBOARD: J31
component class CON_MIDI: J20 J21 J22
component class CON_MOUSE: J32
component class CON_PSU: D10 J19 SW7
component class CON_PWM: J16
component class CON_RELAY: J14
component class CON_RS232: J17
component class CON_RS485: J23
component class CON_SPDIF: C37 C38 D1 D2 J11 J12 R31 R32 R33 R34 R35 R36 R37 R38 T1 U3
component class CON_USB1: J36
component class CON_USB2: J37
component class CON_USB3: J38
component class CON_USB: J10
component class CON_VGA: J18
component class DAC: C117 C118 C119 C120 R149 R150 R151 R152 U28 U29
component class DBUSB_TXRX1: 2222222 C170 C171 C172 C173 C174 C175 C176 C177 NT45 R245 R246 R247 R249 R250 R251 R252 R271 U55 U56 U60
component class DBUSB_TXRX2: C88 C89 C90 C91 C92 C93 C94 C95 NT10 R108 R109 R110 R112 R113 R114 R115 R248 U18 U19 U49
component class ETH: C40 C41 C42 C43 C44 C45 C46 C47 C48 C49 C50 C51 C52 C53 C54 L1 L2 LED3 LED4 LED5 LED6 LED7 R41 R42 R43 R44 R45 R46 R47 R48 R49 R50 R51 R52 R53 R54 R55 R56 R57 R58 R59 R60 R61 R62 R63 R64 R65 R66 R67 U5 U6 Y2
component class GOLDEN: C158 C159 U50
component class HOST_DECOUPLING_CAPS_1V2: C260 C265 C266 C267 C268 C269 C270 C271 C272 C273 C274 C275
component class HOST_DECOUPLING_CAPS_3V3: C276 C277 C278 C279 C291 C292 C293 C294 C295 C296 C297 C298 C299 C300 C301 C302 C303 C304 C305 C307 C308 C309 C310 C311 C312 C313 C314 C315 C316 C317 C318 C319 C320 C321 C322 C323 C324 C325 C326 C327 C328 C329 C330 C331 C332 C333 C334 C335
component class HOST_JTAG: J25
component class HOST_NonIO: R161 R162 R163 R267 R268 R269 R270 R279 R280 R281 R282
component class "JTAG CONFIG": R216 R217 R218 R219 R220 R221 R222 R223 R224 R225 R226 R227 R228 R229 R230 R231 R232 R233
component class KEYBOARD: C61 R82 R83 R84 R85
component class CON_LCDTFT: J27 NT34 NT35 NT36 NT37 NT38 NT39 NT40 NT41 Q11 R100 R101 R214
component class LED_HOST: C121 LED16 LED17 R164 R165 R166 R167 R168 R169 U31
component class "MIDI INTERFACE": D9 NT47 NT48 Q9 Q10 R194 R195 R196 R197 R198 R199 R200 U36 U37 U38
component class MOUNTS: "Altium Logo BOT1" FD1 FD2 FD3 JUMPER1 JUMPER2 JUMPER3 JUMPER4 LOGO1 PB_MH1 PB_MH2 PB_MH3 PB_MH4 PB_MH5 PCB1
component class MOUSE: C62 R86 R87 R88 R89
component class NB_ID: D7 R131 R132 U23
component class PBA: EXTHDR1 R234
component class PDA_SWITCHES: R102 R103 R104 R105 R106 SW1 SW2 SW3 SW4 SW5
component class PSU_1V2: C138 C139 C140 C141 U42
component class PSU_1V8: C126 C127 C128 C129 U39
component class PSU_2V5: C130 C131 C132 C133 U40
component class PSU_3V3: C134 C135 C136 C137 U41
component class PSU_A3V3_ADC1: C142 C143 C144 U43
component class PSU_A3V3_ADC2: C181 C182 C183 U58
component class PSU_A3V3_CODEC: C145 C146 C147 U44
component class PSU: C1 C2 C3 C4 C87 J1 J2 J3 NT1 NT11 NT17 NT18 NT19 R111 TP1 TP2 TP3 TP4 TP5 TP6 TP7 TP8
component class PWM: F1
component class PWRPWM0: LED12 Q5 R123 R124 U22
component class PWRPWM1: LED8 Q1 R90 R91 U9
component class PWRPWM2: LED9 Q2 R92 R93 U10
component class PWRPWM3: LED10 Q3 R94 R95 U11
component class RS232: C148 C149 C150 C151 R209 R210 U59
component class RS485: C152 J26 R211 R212 U46
component class "RT CLOCK": C115 C116 D8 R147 R148 TP11 TP12 U27 Y3
component class SET_1V2: R207 R208
component class SET_1V8: R201 R202
component class SET_2V5: R203 R204
component class SET_3V3: R205 R206
component class Speakers: J34 J35
component class SW_DIP8_SMT: R236 R237 R238 R239 R240 R241 R242 R243 SW8
component class SYSBOOT: C160 C161 U51
component class TEST_RESET: R107 SW6
component class U_Audio_Codec: R98 R154 U45
component class FPGA_HOST: J24 R99 R153 R158 R159 R160 R264 R265 R266 U30
component class FPGA_USER: NT4 NT5 NT6 NT7 NT46 R68 R69 R70 R71 R72 R73 R74 R75 R76 R77 R78 R79 R80 R81 R155 R156 R157 R235 R277 R278 R283 U8
component class U_LED_01: C122 LED18 LED19 R170 R171 R172 R173 R174 R175 U32
component class U_LED_23: C123 LED20 LED21 R176 R177 R178 R179 R180 R181 U33
component class U_LED_45: C124 LED22 LED23 R182 R183 R184 R185 R186 R187 U34
component class U_LED_67: C125 LED24 LED25 R188 R189 R190 R191 R192 R193 U35
component class U_NB2_VIDEO_DAC: C96 C97 C98 C99 C100 L3 R116 R117 R118 R119 R120 R121 R122 U21
component class U_RELAY0: D3 LED11 Q4 R96 R97 RLY1
component class U_RELAY1: D4 LED13 Q6 R125 R126 RLY2
component class U_RELAY2: D5 LED14 Q7 R127 R128 RLY3
component class U_RELAY3: D6 LED15 Q8 R129 R130 RLY4
component class U_SRAM1: C71 C72 C73 C74 U14
component class U_SRAM2: C75 C76 C77 C78 U15
component class U_SRAM_HOST: C153 C154 C155 C156 U47
component class U_USB_CLK: C166 C167 C168 R244 U54 Y4
component class USB_USERHOST: C157 C169 C185 C186 C187 C336 C337 C338 C339 C340 C341 C342 F2 R257 R258 R259 R260 R261 R262 R263 R272 R273 R274 R275 R276 U61 U62 U63 U64 Y5
component class USER_DECOUPLING_CAPS_1V2: C184 C189 C190 C191 C192 C193 C194 C195 C196 C197 C198 C199
component class USER_DECOUPLING_CAPS_3V3: C200 C201 C202 C203 C215 C216 C217 C218 C219 C220 C221 C222 C223 C224 C225 C226 C227 C228 C229 C231 C232 C233 C234 C235 C236 C237 C238 C239 C240 C241 C242 C243 C244 C245 C246 C247 C248 C249 C250 C251 C252 C253 C254 C255 C256 C257 C258 C259
component class USER_FLASH: C162 C163 C164 C165 U52 U53
component class CON_LEDKBD: J28 NT26 NT27 NT28 NT29 NT30 NT31 NT33
component class USER_PROTOTYPE_AREA: PROTOTYPE1
component class VIDEO_OUT: U20
net class ADC#.ADC[3..0]: ADC#.ADC0 ADC#.ADC1 ADC#.ADC2 ADC#.ADC3
net class ADC#: ADC#.ADC0 ADC#.ADC1 ADC#.ADC2 ADC#.ADC3
net class ADC: ADC.CLK ADC.CS ADC.DIN ADC.DOUT
net class AIN: PB_AIN.L PB_AIN.MIC PB_AIN.R
net class AOUT: PB_AOUT.L PB_AOUT.R
net class ATE.DAC#.DAC[3..0]: ATE.DAC#.DAC0 ATE.DAC#.DAC1 ATE.DAC#.DAC2 ATE.DAC#.DAC3
net class ATE.PWM.OUT[3..0]: ATE.PWM.OUT0 ATE.PWM.OUT1 ATE.PWM.OUT2 ATE.PWM.OUT3
net class ATE.UIO.IO[35..0]: ATE.UIO.IO0 ATE.UIO.IO1 ATE.UIO.IO2 ATE.UIO.IO3 ATE.UIO.IO4 ATE.UIO.IO5 ATE.UIO.IO6 ATE.UIO.IO7 ATE.UIO.IO8 ATE.UIO.IO9 ATE.UIO.IO10 ATE.UIO.IO11 ATE.UIO.IO12 ATE.UIO.IO13 ATE.UIO.IO14 ATE.UIO.IO15 ATE.UIO.IO16 ATE.UIO.IO17 ATE.UIO.IO18 ATE.UIO.IO19 ATE.UIO.IO20 ATE.UIO.IO21 ATE.UIO.IO22 ATE.UIO.IO23 ATE.UIO.IO24 ATE.UIO.IO25 ATE.UIO.IO26 ATE.UIO.IO27 ATE.UIO.IO28 ATE.UIO.IO29 ATE.UIO.IO30 ATE.UIO.IO31 ATE.UIO.IO32 ATE.UIO.IO33 ATE.UIO.IO34 ATE.UIO.IO35
net class ATE: ADC#.ADC0 ADC#.ADC1 ADC#.ADC2 ADC#.ADC3 ATE.AUDIO.AMP_L ATE.AUDIO.AMP_R ATE.AUDIO.HP_L ATE.AUDIO.HP_R ATE.AUDIO.HP_SENSE ATE.AUDIO.LIN_L ATE.AUDIO.LIN_R ATE.AUDIO.LOUT_L ATE.AUDIO.LOUT_R ATE.DAC#.DAC0 ATE.DAC#.DAC1 ATE.DAC#.DAC2 ATE.DAC#.DAC3 ATE.HOST_ID.DATA ATE.HOST_ID.EXT_PROG ATE.HOST_JTAG.HARD.TCK ATE.HOST_JTAG.HARD.TDI ATE.HOST_JTAG.HARD.TDO ATE.HOST_JTAG.HARD.TMS ATE.HOST_JTAG.SOFT.TCK ATE.HOST_JTAG.SOFT.TDI ATE.HOST_JTAG.SOFT.TDO ATE.HOST_JTAG.SOFT.TMS ATE.KBD#.CLOCK ATE.KBD#.DATA ATE.MIDI#.MIDI_OUT_PWR ATE.MIDI#.MIDI_RX_N ATE.MIDI#.MIDI_RX_P ATE.MIDI#.MIDI_THRU_GND ATE.MIDI#.MIDI_THRU_PWR ATE.MIDI#.MIDI_THRU_TX ATE.MIDI#.MIDI_TX_GND ATE.MIDI#.MIDI_TX_N ATE.MSE#.CLOCK ATE.MSE#.DATA ATE.PWM.OUT0 ATE.PWM.OUT1 ATE.PWM.OUT2 ATE.PWM.OUT3 ATE.RS232#.CTS ATE.RS232#.DCD ATE.RS232#.RI ATE.RS232#.RTS ATE.RS232#.RXD ATE.RS232#.TXD ATE.RS485#.RX_N ATE.RS485#.RX_P ATE.RS485#.TX_N ATE.RS485#.TX_P ATE.SPDIF.IN ATE.SPDIF.OUT ATE.UIO.IO0 ATE.UIO.IO1 ATE.UIO.IO2 ATE.UIO.IO3 ATE.UIO.IO4 ATE.UIO.IO5 ATE.UIO.IO6 ATE.UIO.IO7 ATE.UIO.IO8 ATE.UIO.IO9 ATE.UIO.IO10 ATE.UIO.IO11 ATE.UIO.IO12 ATE.UIO.IO13 ATE.UIO.IO14 ATE.UIO.IO15 ATE.UIO.IO16 ATE.UIO.IO17 ATE.UIO.IO18 ATE.UIO.IO19 ATE.UIO.IO20 ATE.UIO.IO21 ATE.UIO.IO22 ATE.UIO.IO23 ATE.UIO.IO24 ATE.UIO.IO25 ATE.UIO.IO26 ATE.UIO.IO27 ATE.UIO.IO28 ATE.UIO.IO29 ATE.UIO.IO30 ATE.UIO.IO31 ATE.UIO.IO32 ATE.UIO.IO33 ATE.UIO.IO34 ATE.UIO.IO35 ATE.VGA#.BLUE ATE.VGA#.GREEN ATE.VGA#.HSYNC ATE.VGA#.ID0 ATE.VGA#.ID1/SDA/DDC ATE.VGA#.ID2 ATE.VGA#.ID3/SCL/DDC ATE.VGA#.KEY ATE.VGA#.RED ATE.VGA#.VSYNC
net class AUDIO: ATE.AUDIO.AMP_L ATE.AUDIO.AMP_R ATE.AUDIO.HP_L ATE.AUDIO.HP_R ATE.AUDIO.HP_SENSE ATE.AUDIO.LIN_L ATE.AUDIO.LIN_R ATE.AUDIO.LOUT_L ATE.AUDIO.LOUT_R
net class BOOT_FLASH: BOOT_FLASH.DIN BOOT_FLASH.DOUT BOOT_FLASH.FLASH_CS_N BOOT_FLASH.SCLK
net class CLOCKS: PBCTRL.CLK.CLK0 PBCTRL.CLK.CLK1 PBCTRL.CLK.CLK2 PBCTRL.CLK.EN
net class CM_FLASH: DB_MEM.BUS_A1 DB_MEM.BUS_A2 DB_MEM.BUS_A3 DB_MEM.BUS_A4 DB_MEM.BUS_A5 DB_MEM.BUS_A6 DB_MEM.BUS_A7 DB_MEM.BUS_A8 DB_MEM.BUS_A9 DB_MEM.BUS_A10 DB_MEM.BUS_A11 DB_MEM.BUS_A12 DB_MEM.BUS_A13 DB_MEM.BUS_A14 DB_MEM.BUS_A15 DB_MEM.BUS_A16 DB_MEM.BUS_A17 DB_MEM.BUS_A18 DB_MEM.BUS_A19 DB_MEM.BUS_A20 DB_MEM.BUS_A21 DB_MEM.BUS_A22 DB_MEM.BUS_A23 DB_MEM.BUS_A24 DB_MEM.BUS_D0 DB_MEM.BUS_D1 DB_MEM.BUS_D2 DB_MEM.BUS_D3 DB_MEM.BUS_D4 DB_MEM.BUS_D5 DB_MEM.BUS_D6 DB_MEM.BUS_D7 DB_MEM.BUS_D8 DB_MEM.BUS_D9 DB_MEM.BUS_D10 DB_MEM.BUS_D11 DB_MEM.BUS_D12 DB_MEM.BUS_D13 DB_MEM.BUS_D14 DB_MEM.BUS_D15 DB_MEM.BUS_FLASH_NBUSY DB_MEM.BUS_FLASH_NCS DB_MEM.BUS_FLASH_NRESET DB_MEM.BUS_NOE DB_MEM.BUS_NWE
net class CM_SDRAM: DB_MEM.BUS_A2 DB_MEM.BUS_A3 DB_MEM.BUS_A4 DB_MEM.BUS_A5 DB_MEM.BUS_A6 DB_MEM.BUS_A7 DB_MEM.BUS_A8 DB_MEM.BUS_A9 DB_MEM.BUS_A10 DB_MEM.BUS_A11 DB_MEM.BUS_A12 DB_MEM.BUS_A13 DB_MEM.BUS_A14 DB_MEM.BUS_A15 DB_MEM.BUS_A16 DB_MEM.BUS_D0 DB_MEM.BUS_D1 DB_MEM.BUS_D2 DB_MEM.BUS_D3 DB_MEM.BUS_D4 DB_MEM.BUS_D5 DB_MEM.BUS_D6 DB_MEM.BUS_D7 DB_MEM.BUS_D8 DB_MEM.BUS_D9 DB_MEM.BUS_D10 DB_MEM.BUS_D11 DB_MEM.BUS_D12 DB_MEM.BUS_D13 DB_MEM.BUS_D14 DB_MEM.BUS_D15 DB_MEM.BUS_D16 DB_MEM.BUS_D17 DB_MEM.BUS_D18 DB_MEM.BUS_D19 DB_MEM.BUS_D20 DB_MEM.BUS_D21 DB_MEM.BUS_D22 DB_MEM.BUS_D23 DB_MEM.BUS_D24 DB_MEM.BUS_D25 DB_MEM.BUS_D26 DB_MEM.BUS_D27 DB_MEM.BUS_D28 DB_MEM.BUS_D29 DB_MEM.BUS_D30 DB_MEM.BUS_D31 DB_MEM.BUS_NBE0 DB_MEM.BUS_NBE1 DB_MEM.BUS_NBE2 DB_MEM.BUS_NBE3 DB_MEM.BUS_NWE DB_MEM.BUS_SDRAM_CKE DB_MEM.BUS_SDRAM_CLK DB_MEM.BUS_SDRAM_NCAS DB_MEM.BUS_SDRAM_NCS DB_MEM.BUS_SDRAM_NRAS
net class CM_SRAM: DB_MEM.BUS_A2 DB_MEM.BUS_A3 DB_MEM.BUS_A4 DB_MEM.BUS_A5 DB_MEM.BUS_A6 DB_MEM.BUS_A7 DB_MEM.BUS_A8 DB_MEM.BUS_A9 DB_MEM.BUS_A10 DB_MEM.BUS_A11 DB_MEM.BUS_A12 DB_MEM.BUS_A13 DB_MEM.BUS_A14 DB_MEM.BUS_A15 DB_MEM.BUS_A16 DB_MEM.BUS_A17 DB_MEM.BUS_A18 DB_MEM.BUS_A19 DB_MEM.BUS_A20 DB_MEM.BUS_D0 DB_MEM.BUS_D1 DB_MEM.BUS_D2 DB_MEM.BUS_D3 DB_MEM.BUS_D4 DB_MEM.BUS_D5 DB_MEM.BUS_D6 DB_MEM.BUS_D7 DB_MEM.BUS_D8 DB_MEM.BUS_D9 DB_MEM.BUS_D10 DB_MEM.BUS_D11 DB_MEM.BUS_D12 DB_MEM.BUS_D13 DB_MEM.BUS_D14 DB_MEM.BUS_D15 DB_MEM.BUS_D16 DB_MEM.BUS_D17 DB_MEM.BUS_D18 DB_MEM.BUS_D19 DB_MEM.BUS_D20 DB_MEM.BUS_D21 DB_MEM.BUS_D22 DB_MEM.BUS_D23 DB_MEM.BUS_D24 DB_MEM.BUS_D25 DB_MEM.BUS_D26 DB_MEM.BUS_D27 DB_MEM.BUS_D28 DB_MEM.BUS_D29 DB_MEM.BUS_D30 DB_MEM.BUS_D31 DB_MEM.BUS_NBE0 DB_MEM.BUS_NBE1 DB_MEM.BUS_NBE2 DB_MEM.BUS_NBE3 DB_MEM.BUS_NOE DB_MEM.BUS_NWE DB_MEM.BUS_SRAM_NCS
net class CODEC: CODEC.I2S_BCLK CODEC.I2S_DIN CODEC.I2S_DOUT CODEC.I2S_MCLK CODEC.I2S_WCLK CODEC.SPI_CLK CODEC.SPI_CS_N CODEC.SPI_DIN CODEC.SPI_DOUT
net class DAC#: ATE.DAC#.DAC0 ATE.DAC#.DAC1 ATE.DAC#.DAC2 ATE.DAC#.DAC3
net class DAC: DAC.CLK DAC.CS DAC.DIN
net class DB_CLOCKS: DB_CLOCKS.FPGA_CLK DB_CLOCKS.FPGA_CLK1 DB_CLOCKS.REF_CLK
net class DB_JTAG: DB_JTAG.HARD.TCK DB_JTAG.HARD.TDI DB_JTAG.HARD.TDO DB_JTAG.HARD.TMS DB_JTAG.SOFT.TCK DB_JTAG.SOFT.TDI DB_JTAG.SOFT.TDO DB_JTAG.SOFT.TMS
net class DB_MEM.BUS_A[24..1]: DB_MEM.BUS_A1 DB_MEM.BUS_A2 DB_MEM.BUS_A3 DB_MEM.BUS_A4 DB_MEM.BUS_A5 DB_MEM.BUS_A6 DB_MEM.BUS_A7 DB_MEM.BUS_A8 DB_MEM.BUS_A9 DB_MEM.BUS_A10 DB_MEM.BUS_A11 DB_MEM.BUS_A12 DB_MEM.BUS_A13 DB_MEM.BUS_A14 DB_MEM.BUS_A15 DB_MEM.BUS_A16 DB_MEM.BUS_A17 DB_MEM.BUS_A18 DB_MEM.BUS_A19 DB_MEM.BUS_A20 DB_MEM.BUS_A21 DB_MEM.BUS_A22 DB_MEM.BUS_A23 DB_MEM.BUS_A24
net class DB_MEM.BUS_D[31..0]: DB_MEM.BUS_D0 DB_MEM.BUS_D1 DB_MEM.BUS_D2 DB_MEM.BUS_D3 DB_MEM.BUS_D4 DB_MEM.BUS_D5 DB_MEM.BUS_D6 DB_MEM.BUS_D7 DB_MEM.BUS_D8 DB_MEM.BUS_D9 DB_MEM.BUS_D10 DB_MEM.BUS_D11 DB_MEM.BUS_D12 DB_MEM.BUS_D13 DB_MEM.BUS_D14 DB_MEM.BUS_D15 DB_MEM.BUS_D16 DB_MEM.BUS_D17 DB_MEM.BUS_D18 DB_MEM.BUS_D19 DB_MEM.BUS_D20 DB_MEM.BUS_D21 DB_MEM.BUS_D22 DB_MEM.BUS_D23 DB_MEM.BUS_D24 DB_MEM.BUS_D25 DB_MEM.BUS_D26 DB_MEM.BUS_D27 DB_MEM.BUS_D28 DB_MEM.BUS_D29 DB_MEM.BUS_D30 DB_MEM.BUS_D31
net class DB_MEM.BUS_NBE[3..0]: DB_MEM.BUS_NBE0 DB_MEM.BUS_NBE1 DB_MEM.BUS_NBE2 DB_MEM.BUS_NBE3
net class DB_MEM: DB_MEM.BUS_A1 DB_MEM.BUS_A2 DB_MEM.BUS_A3 DB_MEM.BUS_A4 DB_MEM.BUS_A5 DB_MEM.BUS_A6 DB_MEM.BUS_A7 DB_MEM.BUS_A8 DB_MEM.BUS_A9 DB_MEM.BUS_A10 DB_MEM.BUS_A11 DB_MEM.BUS_A12 DB_MEM.BUS_A13 DB_MEM.BUS_A14 DB_MEM.BUS_A15 DB_MEM.BUS_A16 DB_MEM.BUS_A17 DB_MEM.BUS_A18 DB_MEM.BUS_A19 DB_MEM.BUS_A20 DB_MEM.BUS_A21 DB_MEM.BUS_A22 DB_MEM.BUS_A23 DB_MEM.BUS_A24 DB_MEM.BUS_D0 DB_MEM.BUS_D1 DB_MEM.BUS_D2 DB_MEM.BUS_D3 DB_MEM.BUS_D4 DB_MEM.BUS_D5 DB_MEM.BUS_D6 DB_MEM.BUS_D7 DB_MEM.BUS_D8 DB_MEM.BUS_D9 DB_MEM.BUS_D10 DB_MEM.BUS_D11 DB_MEM.BUS_D12 DB_MEM.BUS_D13 DB_MEM.BUS_D14 DB_MEM.BUS_D15 DB_MEM.BUS_D16 DB_MEM.BUS_D17 DB_MEM.BUS_D18 DB_MEM.BUS_D19 DB_MEM.BUS_D20 DB_MEM.BUS_D21 DB_MEM.BUS_D22 DB_MEM.BUS_D23 DB_MEM.BUS_D24 DB_MEM.BUS_D25 DB_MEM.BUS_D26 DB_MEM.BUS_D27 DB_MEM.BUS_D28 DB_MEM.BUS_D29 DB_MEM.BUS_D30 DB_MEM.BUS_D31 DB_MEM.BUS_FLASH_NBUSY DB_MEM.BUS_FLASH_NCS DB_MEM.BUS_FLASH_NRESET DB_MEM.BUS_NBE0 DB_MEM.BUS_NBE1 DB_MEM.BUS_NBE2 DB_MEM.BUS_NBE3 DB_MEM.BUS_NOE DB_MEM.BUS_NWE DB_MEM.BUS_SDRAM_CKE DB_MEM.BUS_SDRAM_CLK DB_MEM.BUS_SDRAM_NCAS DB_MEM.BUS_SDRAM_NCS DB_MEM.BUS_SDRAM_NRAS DB_MEM.BUS_SRAM_NCS
net class DB_PROGRAM.ID[3..0]: DB_PROGRAM.ID0 DB_PROGRAM.ID1 DB_PROGRAM.ID2 DB_PROGRAM.ID3
net class DB_PROGRAM.M[2..0]: DB_PROGRAM.M0 DB_PROGRAM.M1 DB_PROGRAM.M2
net class DB_PROGRAM: DB_PROGRAM.CCLK DB_PROGRAM.DIN DB_PROGRAM.DONE DB_PROGRAM.ID0 DB_PROGRAM.ID1 DB_PROGRAM.ID2 DB_PROGRAM.ID3 DB_PROGRAM.INIT DB_PROGRAM.INSTALLED DB_PROGRAM.M0 DB_PROGRAM.M1 DB_PROGRAM.M2 DB_PROGRAM.PROG_CLK DB_PROGRAM.PROG_PWR_ON DB_PROGRAM.PROGRAM
net class DB_SPI: DB_SPI.CLK DB_SPI.DIN DB_SPI.DOUT DB_SPI.MODE DB_SPI.SEL
net class DB_SRAM1.A[18..0]: DB_SRAM1.A0 DB_SRAM1.A1 DB_SRAM1.A2 DB_SRAM1.A3 DB_SRAM1.A4 DB_SRAM1.A5 DB_SRAM1.A6 DB_SRAM1.A7 DB_SRAM1.A8 DB_SRAM1.A9 DB_SRAM1.A10 DB_SRAM1.A11 DB_SRAM1.A12 DB_SRAM1.A13 DB_SRAM1.A14 DB_SRAM1.A15 DB_SRAM1.A16 DB_SRAM1.A17 DB_SRAM1.A18
net class DB_SRAM1.D[15..0]: DB_SRAM1.D0 DB_SRAM1.D1 DB_SRAM1.D2 DB_SRAM1.D3 DB_SRAM1.D4 DB_SRAM1.D5 DB_SRAM1.D6 DB_SRAM1.D7 DB_SRAM1.D8 DB_SRAM1.D9 DB_SRAM1.D10 DB_SRAM1.D11 DB_SRAM1.D12 DB_SRAM1.D13 DB_SRAM1.D14 DB_SRAM1.D15
net class DB_SRAM1: DB_SRAM1.A0 DB_SRAM1.A1 DB_SRAM1.A2 DB_SRAM1.A3 DB_SRAM1.A4 DB_SRAM1.A5 DB_SRAM1.A6 DB_SRAM1.A7 DB_SRAM1.A8 DB_SRAM1.A9 DB_SRAM1.A10 DB_SRAM1.A11 DB_SRAM1.A12 DB_SRAM1.A13 DB_SRAM1.A14 DB_SRAM1.A15 DB_SRAM1.A16 DB_SRAM1.A17 DB_SRAM1.A18 DB_SRAM1.D0 DB_SRAM1.D1 DB_SRAM1.D2 DB_SRAM1.D3 DB_SRAM1.D4 DB_SRAM1.D5 DB_SRAM1.D6 DB_SRAM1.D7 DB_SRAM1.D8 DB_SRAM1.D9 DB_SRAM1.D10 DB_SRAM1.D11 DB_SRAM1.D12 DB_SRAM1.D13 DB_SRAM1.D14 DB_SRAM1.D15 DB_SRAM1.NBHE DB_SRAM1.NBLE DB_SRAM1.NCS DB_SRAM1.NOE DB_SRAM1.NWE
net class DB_SRAM2.A[18..0]: DB_SRAM2.A0 DB_SRAM2.A1 DB_SRAM2.A2 DB_SRAM2.A3 DB_SRAM2.A4 DB_SRAM2.A5 DB_SRAM2.A6 DB_SRAM2.A7 DB_SRAM2.A8 DB_SRAM2.A9 DB_SRAM2.A10 DB_SRAM2.A11 DB_SRAM2.A12 DB_SRAM2.A13 DB_SRAM2.A14 DB_SRAM2.A15 DB_SRAM2.A16 DB_SRAM2.A17 DB_SRAM2.A18
net class DB_SRAM2.D[15..0]: DB_SRAM2.D0 DB_SRAM2.D1 DB_SRAM2.D2 DB_SRAM2.D3 DB_SRAM2.D4 DB_SRAM2.D5 DB_SRAM2.D6 DB_SRAM2.D7 DB_SRAM2.D8 DB_SRAM2.D9 DB_SRAM2.D10 DB_SRAM2.D11 DB_SRAM2.D12 DB_SRAM2.D13 DB_SRAM2.D14 DB_SRAM2.D15
net class DB_SRAM2: DB_SRAM2.A0 DB_SRAM2.A1 DB_SRAM2.A2 DB_SRAM2.A3 DB_SRAM2.A4 DB_SRAM2.A5 DB_SRAM2.A6 DB_SRAM2.A7 DB_SRAM2.A8 DB_SRAM2.A9 DB_SRAM2.A10 DB_SRAM2.A11 DB_SRAM2.A12 DB_SRAM2.A13 DB_SRAM2.A14 DB_SRAM2.A15 DB_SRAM2.A16 DB_SRAM2.A17 DB_SRAM2.A18 DB_SRAM2.D0 DB_SRAM2.D1 DB_SRAM2.D2 DB_SRAM2.D3 DB_SRAM2.D4 DB_SRAM2.D5 DB_SRAM2.D6 DB_SRAM2.D7 DB_SRAM2.D8 DB_SRAM2.D9 DB_SRAM2.D10 DB_SRAM2.D11 DB_SRAM2.D12 DB_SRAM2.D13 DB_SRAM2.D14 DB_SRAM2.D15 DB_SRAM2.NBHE DB_SRAM2.NBLE DB_SRAM2.NCS DB_SRAM2.NOE DB_SRAM2.NWE
net class DBSD.DAT[3..0]: DBSD.DAT0 DBSD.DAT1 DBSD.DAT2 DBSD.DAT3
net class DBSD: DBSD.CLK DBSD.CMD DBSD.DAT0 DBSD.DAT1 DBSD.DAT2 DBSD.DAT3 DBSD.DETECT DBSD.PROTECT
net class DBUSB#: DBUSB#.DMINUS DBUSB#.DPLUS DBUSB#.VBUS
net class DBUSB.D[15..0]: DBUSB.D0 DBUSB.D1 DBUSB.D2 DBUSB.D3 DBUSB.D4 DBUSB.D5 DBUSB.D6 DBUSB.D7 DBUSB.D8 DBUSB.D9 DBUSB.D10 DBUSB.D11 DBUSB.D12 DBUSB.D13 DBUSB.D14 DBUSB.D15
net class DBUSB: DBUSB.D0 DBUSB.D1 DBUSB.D2 DBUSB.D3 DBUSB.D4 DBUSB.D5 DBUSB.D6 DBUSB.D7 DBUSB.D8 DBUSB.D9 DBUSB.D10 DBUSB.D11 DBUSB.D12 DBUSB.D13 DBUSB.D14 DBUSB.D15 DBUSB.FIFOADR0 DBUSB.FIFOADR1 DBUSB.FIFOADR2 DBUSB.FLAGA DBUSB.FLAGB DBUSB.FLAGC DBUSB.FLAGD_CS_N DBUSB.IFCLK DBUSB.INT_N DBUSB.PKTEND DBUSB.RD_N DBUSB.READY DBUSB.RESET_N DBUSB.SLOE DBUSB.VBUS DBUSB.WR_N DBUSB.XTALIN DBUSB.XTALOUT
net class DIAGCOMMS: DIAGCOMMS.DIN DIAGCOMMS.DOUT DIAGCOMMS.FLASH_CS_N DIAGCOMMS.SCLK
net class DIPSW.D[7..0]: DIPSW.D0 DIPSW.D1 DIPSW.D2 DIPSW.D3 DIPSW.D4 DIPSW.D5 DIPSW.D6 DIPSW.D7
net class DIPSW: DIPSW.D0 DIPSW.D1 DIPSW.D2 DIPSW.D3 DIPSW.D4 DIPSW.D5 DIPSW.D6 DIPSW.D7
net class ETH#: ETH#.ACT_A ETH#.LINK_K ETH#.RX_CT ETH#.RX_N ETH#.RX_P ETH#.TX_N ETH#.TX_P
net class ETH.E_RXD[3..0]: ETH.E_RXD0 ETH.E_RXD1 ETH.E_RXD2 ETH.E_RXD3
net class ETH.E_TXD[3..0]: ETH.E_TXD0 ETH.E_TXD1 ETH.E_TXD2 ETH.E_TXD3
net class "Ethernet Interface": ETH.E_COL ETH.E_CRS ETH.E_MDC ETH.E_MDIO ETH.E_RESETB_E ETH.E_RXC ETH.E_RXD0 ETH.E_RXD1 ETH.E_RXD2 ETH.E_RXD3 ETH.E_RXDV ETH.E_RXER ETH.E_TXC ETH.E_TXD0 ETH.E_TXD1 ETH.E_TXD2 ETH.E_TXD3 ETH.E_TXEN
net class ETH: ETH.E_COL ETH.E_CRS ETH.E_MDC ETH.E_MDIO ETH.E_RESETB_E ETH.E_RXC ETH.E_RXD0 ETH.E_RXD1 ETH.E_RXD2 ETH.E_RXD3 ETH.E_RXDV ETH.E_RXER ETH.E_TXC ETH.E_TXD0 ETH.E_TXD1 ETH.E_TXD2 ETH.E_TXD3 ETH.E_TXEN
net class GOLD_FLASH: GOLD_FLASH.DIN GOLD_FLASH.DOUT GOLD_FLASH.FLASH_CS_N GOLD_FLASH.SCLK
net class HOST_AUDIO: HOST_AUDIO.L HOST_AUDIO.R
net class HOST_CLK: DB_CLOCKS.FPGA_CLK DB_CLOCKS.REF_CLK HOST_CLK.CS_N HOST_CLK.DIN HOST_CLK.SCLK
net class HOST_ID: ATE.HOST_ID.DATA ATE.HOST_ID.EXT_PROG
net class HOST_JTAG: ATE.HOST_JTAG.HARD.TCK ATE.HOST_JTAG.HARD.TDI ATE.HOST_JTAG.HARD.TDO ATE.HOST_JTAG.HARD.TMS ATE.HOST_JTAG.SOFT.TCK ATE.HOST_JTAG.SOFT.TDI ATE.HOST_JTAG.SOFT.TDO ATE.HOST_JTAG.SOFT.TMS
net class HOST_LED1: HOST_LED1.BLUE HOST_LED1.GREEN HOST_LED1.RED
net class HOST_LED2: HOST_LED2.BLUE HOST_LED2.GREEN HOST_LED2.RED
net class HOST_RTC: HOST_RTC.CLKOE HOST_RTC.CLKOUT HOST_RTC.CS_N HOST_RTC.DIN HOST_RTC.DOUT HOST_RTC.INT_N HOST_RTC.SCLK
net class HOST_SD.DAT[3..0]: HOST_SD.DAT0 HOST_SD.DAT1 HOST_SD.DAT2 HOST_SD.DAT3
net class HOST_SD: HOST_SD.CLK HOST_SD.CMD HOST_SD.DAT0 HOST_SD.DAT1 HOST_SD.DAT2 HOST_SD.DAT3 HOST_SD.DETECT HOST_SD.PROTECT
net class HOST_SRAM.A[18..0]: HOST_SRAM.A0 HOST_SRAM.A1 HOST_SRAM.A2 HOST_SRAM.A3 HOST_SRAM.A4 HOST_SRAM.A5 HOST_SRAM.A6 HOST_SRAM.A7 HOST_SRAM.A8 HOST_SRAM.A9 HOST_SRAM.A10 HOST_SRAM.A11 HOST_SRAM.A12 HOST_SRAM.A13 HOST_SRAM.A14 HOST_SRAM.A15 HOST_SRAM.A16 HOST_SRAM.A17 HOST_SRAM.A18
net class HOST_SRAM.D[15..0]: HOST_SRAM.D0 HOST_SRAM.D1 HOST_SRAM.D2 HOST_SRAM.D3 HOST_SRAM.D4 HOST_SRAM.D5 HOST_SRAM.D6 HOST_SRAM.D7 HOST_SRAM.D8 HOST_SRAM.D9 HOST_SRAM.D10 HOST_SRAM.D11 HOST_SRAM.D12 HOST_SRAM.D13 HOST_SRAM.D14 HOST_SRAM.D15
net class HOST_SRAM: HOST_SRAM.A0 HOST_SRAM.A1 HOST_SRAM.A2 HOST_SRAM.A3 HOST_SRAM.A4 HOST_SRAM.A5 HOST_SRAM.A6 HOST_SRAM.A7 HOST_SRAM.A8 HOST_SRAM.A9 HOST_SRAM.A10 HOST_SRAM.A11 HOST_SRAM.A12 HOST_SRAM.A13 HOST_SRAM.A14 HOST_SRAM.A15 HOST_SRAM.A16 HOST_SRAM.A17 HOST_SRAM.A18 HOST_SRAM.D0 HOST_SRAM.D1 HOST_SRAM.D2 HOST_SRAM.D3 HOST_SRAM.D4 HOST_SRAM.D5 HOST_SRAM.D6 HOST_SRAM.D7 HOST_SRAM.D8 HOST_SRAM.D9 HOST_SRAM.D10 HOST_SRAM.D11 HOST_SRAM.D12 HOST_SRAM.D13 HOST_SRAM.D14 HOST_SRAM.D15 HOST_SRAM.NBHE HOST_SRAM.NBLE HOST_SRAM.NCS HOST_SRAM.NOE HOST_SRAM.NWE
net class HOST_USB.D[15..0]: HOST_USB.D0 HOST_USB.D1 HOST_USB.D2 HOST_USB.D3 HOST_USB.D4 HOST_USB.D5 HOST_USB.D6 HOST_USB.D7 HOST_USB.D8 HOST_USB.D9 HOST_USB.D10 HOST_USB.D11 HOST_USB.D12 HOST_USB.D13 HOST_USB.D14 HOST_USB.D15
net class HOST_USB: HOST_USB.D0 HOST_USB.D1 HOST_USB.D2 HOST_USB.D3 HOST_USB.D4 HOST_USB.D5 HOST_USB.D6 HOST_USB.D7 HOST_USB.D8 HOST_USB.D9 HOST_USB.D10 HOST_USB.D11 HOST_USB.D12 HOST_USB.D13 HOST_USB.D14 HOST_USB.D15 HOST_USB.FIFOADR0 HOST_USB.FIFOADR1 HOST_USB.FIFOADR2 HOST_USB.FLAGA HOST_USB.FLAGB HOST_USB.FLAGC HOST_USB.FLAGD_CS_N HOST_USB.IFCLK HOST_USB.INT_N HOST_USB.PKTEND HOST_USB.RD_N HOST_USB.READY HOST_USB.RESET_N HOST_USB.SLOE HOST_USB.VBUS HOST_USB.WR_N HOST_USB.XTALIN HOST_USB.XTALOUT
net class HOSTUSB#: HOSTUSB#.DMINUS HOSTUSB#.DPLUS HOSTUSB#.VBUS
net class I2C: I2C.SCL I2C.SDA
net class ISP176X: DB_MEM.BUS_A1 DB_MEM.BUS_A2 DB_MEM.BUS_A3 DB_MEM.BUS_A4 DB_MEM.BUS_A5 DB_MEM.BUS_A6 DB_MEM.BUS_A7 DB_MEM.BUS_A8 DB_MEM.BUS_A9 DB_MEM.BUS_A10 DB_MEM.BUS_A11 DB_MEM.BUS_A12 DB_MEM.BUS_A13 DB_MEM.BUS_A14 DB_MEM.BUS_A15 DB_MEM.BUS_A16 DB_MEM.BUS_A17 DB_MEM.BUS_D0 DB_MEM.BUS_D1 DB_MEM.BUS_D2 DB_MEM.BUS_D3 DB_MEM.BUS_D4 DB_MEM.BUS_D5 DB_MEM.BUS_D6 DB_MEM.BUS_D7 DB_MEM.BUS_D8 DB_MEM.BUS_D9 DB_MEM.BUS_D10 DB_MEM.BUS_D11 DB_MEM.BUS_D12 DB_MEM.BUS_D13 DB_MEM.BUS_D14 DB_MEM.BUS_D15 DB_MEM.BUS_D16 DB_MEM.BUS_D17 DB_MEM.BUS_D18 DB_MEM.BUS_D19 DB_MEM.BUS_D20 DB_MEM.BUS_D21 DB_MEM.BUS_D22 DB_MEM.BUS_D23 DB_MEM.BUS_D24 DB_MEM.BUS_D25 DB_MEM.BUS_D26 DB_MEM.BUS_D27 DB_MEM.BUS_D28 DB_MEM.BUS_D29 DB_MEM.BUS_D30 DB_MEM.BUS_D31 DB_MEM.BUS_NOE DB_MEM.BUS_NWE ISP176X.BUS_DMA_ACK ISP176X.BUS_DMA_REQ ISP176X.BUS_NCS ISP176X.BUS_NIRQ ISP176X.ISP176X_NRESET
net class JTAG: JTAG.DETECT JTAG.HARD.TCK JTAG.HARD.TDI JTAG.HARD.TDO JTAG.HARD.TMS JTAG.SOFT.TCK JTAG.SOFT.TDI JTAG.SOFT.TDO JTAG.SOFT.TMS
net class KBD#: ATE.KBD#.CLOCK ATE.KBD#.DATA
net class KEYBOARD: KEYBOARD.CLOCK KEYBOARD.DATA
net class LEDS#: LEDS#.LED0.BLUE LEDS#.LED0.GREEN LEDS#.LED0.RED LEDS#.LED1.BLUE LEDS#.LED1.GREEN LEDS#.LED1.RED LEDS#.LED2.BLUE LEDS#.LED2.GREEN LEDS#.LED2.RED LEDS#.LED3.BLUE LEDS#.LED3.GREEN LEDS#.LED3.RED LEDS#.LED4.BLUE LEDS#.LED4.GREEN LEDS#.LED4.RED LEDS#.LED5.BLUE LEDS#.LED5.GREEN LEDS#.LED5.RED LEDS#.LED6.BLUE LEDS#.LED6.GREEN LEDS#.LED6.RED LEDS#.LED7.BLUE LEDS#.LED7.GREEN LEDS#.LED7.RED NetJ28_7 NetJ28_14 NetJ28_24 NetJ28_26 NetJ28_29 NetJ28_31 NetJ28_33
net class MIDI#: ATE.MIDI#.MIDI_OUT_PWR ATE.MIDI#.MIDI_RX_N ATE.MIDI#.MIDI_RX_P ATE.MIDI#.MIDI_THRU_GND ATE.MIDI#.MIDI_THRU_PWR ATE.MIDI#.MIDI_THRU_TX ATE.MIDI#.MIDI_TX_GND ATE.MIDI#.MIDI_TX_N
net class MIDI: MIDI.MIDI_RX MIDI.MIDI_TX
net class MOUSE: MOUSE.CLOCK MOUSE.DATA
net class MSE#: ATE.MSE#.CLOCK ATE.MSE#.DATA
net class ONE_WIRE: PBCTRL.1W.ID PBCTRL.1W.PIO1 PBCTRL.1W.PIO2
net class PB_AIN: PB_AIN.L PB_AIN.MIC PB_AIN.R
net class PB_AOUT: PB_AOUT.L PB_AOUT.R
net class PB_SPI: PB_SPI.DIN PB_SPI.DOUT PB_SPI.SCLK
net class PBCTRL.1W.PIO[1..2]: PBCTRL.1W.PIO1 PBCTRL.1W.PIO2
net class PBCTRL.CLK.CLK[2..0]: PBCTRL.CLK.CLK0 PBCTRL.CLK.CLK1 PBCTRL.CLK.CLK2
net class PBCTRL.SPARE[1..4]: PBCTRL.SPARE1 PBCTRL.SPARE2 PBCTRL.SPARE3 PBCTRL.SPARE4
net class PBCTRL.SPI_CS_N[1..0]: PBCTRL.SPI_CS_N0 PBCTRL.SPI_CS_N1
net class PBCTRL: PBCTRL.1W.ID PBCTRL.1W.PIO1 PBCTRL.1W.PIO2 PBCTRL.CLK.CLK0 PBCTRL.CLK.CLK1 PBCTRL.CLK.CLK2 PBCTRL.CLK.EN PBCTRL.JTAG.DETECT PBCTRL.JTAG.HARD.TCK PBCTRL.JTAG.HARD.TDI PBCTRL.JTAG.HARD.TDO PBCTRL.JTAG.HARD.TMS PBCTRL.JTAG.SOFT.TCK PBCTRL.JTAG.SOFT.TDI PBCTRL.JTAG.SOFT.TDO PBCTRL.JTAG.SOFT.TMS PBCTRL.SPARE1 PBCTRL.SPARE2 PBCTRL.SPARE3 PBCTRL.SPARE4 PBCTRL.SPI_CS_N0 PBCTRL.SPI_CS_N1
net class PBIO.D[49..0]: PBIO.D0 PBIO.D1 PBIO.D2 PBIO.D3 PBIO.D4 PBIO.D5 PBIO.D6 PBIO.D7 PBIO.D8 PBIO.D9 PBIO.D10 PBIO.D11 PBIO.D12 PBIO.D13 PBIO.D14 PBIO.D15 PBIO.D16 PBIO.D17 PBIO.D18 PBIO.D19 PBIO.D20 PBIO.D21 PBIO.D22 PBIO.D23 PBIO.D24 PBIO.D25 PBIO.D26 PBIO.D27 PBIO.D28 PBIO.D29 PBIO.D30 PBIO.D31 PBIO.D32 PBIO.D33 PBIO.D34 PBIO.D35 PBIO.D36 PBIO.D37 PBIO.D38 PBIO.D39 PBIO.D40 PBIO.D41 PBIO.D42 PBIO.D43 PBIO.D44 PBIO.D45 PBIO.D46 PBIO.D47 PBIO.D48 PBIO.D49
net class PBIO: PBIO.D0 PBIO.D1 PBIO.D2 PBIO.D3 PBIO.D4 PBIO.D5 PBIO.D6 PBIO.D7 PBIO.D8 PBIO.D9 PBIO.D10 PBIO.D11 PBIO.D12 PBIO.D13 PBIO.D14 PBIO.D15 PBIO.D16 PBIO.D17 PBIO.D18 PBIO.D19 PBIO.D20 PBIO.D21 PBIO.D22 PBIO.D23 PBIO.D24 PBIO.D25 PBIO.D26 PBIO.D27 PBIO.D28 PBIO.D29 PBIO.D30 PBIO.D31 PBIO.D32 PBIO.D33 PBIO.D34 PBIO.D35 PBIO.D36 PBIO.D37 PBIO.D38 PBIO.D39 PBIO.D40 PBIO.D41 PBIO.D42 PBIO.D43 PBIO.D44 PBIO.D45 PBIO.D46 PBIO.D47 PBIO.D48 PBIO.D49
net class PORT1: PORT1.DMINUS PORT1.DPLUS PORT1.VBUS
net class PORT2: PORT1.VBUS PORT2.DMINUS PORT2.DPLUS
net class PORT3: PORT1.VBUS PORT3.DMINUS PORT3.DPLUS
net class PROTOTYPE: ATE.UIO.IO0 ATE.UIO.IO1 ATE.UIO.IO2 ATE.UIO.IO3 ATE.UIO.IO4 ATE.UIO.IO5 ATE.UIO.IO6 ATE.UIO.IO7 ATE.UIO.IO8 ATE.UIO.IO9 ATE.UIO.IO10 ATE.UIO.IO11 ATE.UIO.IO12 ATE.UIO.IO13 ATE.UIO.IO14 ATE.UIO.IO15 ATE.UIO.IO16 ATE.UIO.IO17 ATE.UIO.IO18 ATE.UIO.IO19 ATE.UIO.IO20 ATE.UIO.IO21 ATE.UIO.IO22 ATE.UIO.IO23 ATE.UIO.IO24 ATE.UIO.IO25 ATE.UIO.IO26 ATE.UIO.IO27 ATE.UIO.IO28 ATE.UIO.IO29 ATE.UIO.IO30 ATE.UIO.IO31 ATE.UIO.IO32 ATE.UIO.IO33 ATE.UIO.IO34 ATE.UIO.IO35
net class PWM#: ATE.PWM.OUT0 ATE.PWM.OUT1 ATE.PWM.OUT2 ATE.PWM.OUT3
net class PWM: PWM.PWM0 PWM.PWM1 PWM.PWM2 PWM.PWM3
net class PWRNET: 5V0 AUGND GND
net class RELAY.RELAY[3..0]: RELAY.RELAY0 RELAY.RELAY1 RELAY.RELAY2 RELAY.RELAY3
net class RELAYS#: RELAYS#.C0 RELAYS#.C1 RELAYS#.C2 RELAYS#.C3 RELAYS#.NC0 RELAYS#.NC1 RELAYS#.NC2 RELAYS#.NC3 RELAYS#.NO0 RELAYS#.NO1 RELAYS#.NO2 RELAYS#.NO3
net class RELAY: RELAY.RELAY0 RELAY.RELAY1 RELAY.RELAY2 RELAY.RELAY3
net class RS232#: ATE.RS232#.CTS ATE.RS232#.DCD ATE.RS232#.RI ATE.RS232#.RTS ATE.RS232#.RXD ATE.RS232#.TXD
net class RS232: RS232.CTS RS232.RTS RS232.RXD RS232.TXD
net class RS485#: ATE.RS485#.RX_N ATE.RS485#.RX_P ATE.RS485#.TX_N ATE.RS485#.TX_P
net class RS485: RS485.RX_EN RS485.RXD RS485.TX_EN RS485.TXD
net class S_LED[4..0]: S_LED0 S_LED1 S_LED2 S_LED3 S_LED4
net class SPAREIO: SPAREIO.1 SPAREIO.2 SPAREIO.3 SPAREIO.4
net class SPDIF: ATE.SPDIF.IN ATE.SPDIF.OUT
net class SPI: PB_SPI.DIN PB_SPI.DOUT PB_SPI.SCLK
net class SPK_L: SPK_L.SPK+ SPK_L.SPK-
net class SPK_R: SPK_R.SPK+ SPK_R.SPK-
net class SW#.D[4..0]: SW#.D0 SW#.D1 SW#.D2 SW#.D3 SW#.D4
net class SW#: SW#.D0 SW#.D1 SW#.D2 SW#.D3 SW#.D4
net class SW: SW#.D0 SW#.D1 SW#.D2 SW#.D3 SW#.D4
net class TFT_IO.DB[17..0]: TFT_IO.DB0 TFT_IO.DB1 TFT_IO.DB2 TFT_IO.DB3 TFT_IO.DB4 TFT_IO.DB5 TFT_IO.DB6 TFT_IO.DB7 TFT_IO.DB8 TFT_IO.DB9 TFT_IO.DB10 TFT_IO.DB11 TFT_IO.DB12 TFT_IO.DB13 TFT_IO.DB14 TFT_IO.DB15 TFT_IO.DB16 TFT_IO.DB17
net class TFT_IO: TFT_IO.BL TFT_IO.CS TFT_IO.DB0 TFT_IO.DB1 TFT_IO.DB2 TFT_IO.DB3 TFT_IO.DB4 TFT_IO.DB5 TFT_IO.DB6 TFT_IO.DB7 TFT_IO.DB8 TFT_IO.DB9 TFT_IO.DB10 TFT_IO.DB11 TFT_IO.DB12 TFT_IO.DB13 TFT_IO.DB14 TFT_IO.DB15 TFT_IO.DB16 TFT_IO.DB17 TFT_IO.IR38KRX TFT_IO.IR38KTX TFT_IO.RD TFT_IO.RESET TFT_IO.RS TFT_IO.WR TFT_TSC.TFT_INT
net class TFT_TSC: TFT_TSC.BUSY TFT_TSC.CLK TFT_TSC.CS_N TFT_TSC.DIN TFT_TSC.DOUT
net class UIO_PWR: UIO_PWR.AIN UIO_PWR.BIN
net class UIO: ATE.UIO.IO0 ATE.UIO.IO1 ATE.UIO.IO2 ATE.UIO.IO3 ATE.UIO.IO4 ATE.UIO.IO5 ATE.UIO.IO6 ATE.UIO.IO7 ATE.UIO.IO8 ATE.UIO.IO9 ATE.UIO.IO10 ATE.UIO.IO11 ATE.UIO.IO12 ATE.UIO.IO13 ATE.UIO.IO14 ATE.UIO.IO15 ATE.UIO.IO16 ATE.UIO.IO17 ATE.UIO.IO18 ATE.UIO.IO19 ATE.UIO.IO20 ATE.UIO.IO21 ATE.UIO.IO22 ATE.UIO.IO23 ATE.UIO.IO24 ATE.UIO.IO25 ATE.UIO.IO26 ATE.UIO.IO27 ATE.UIO.IO28 ATE.UIO.IO29 ATE.UIO.IO30 ATE.UIO.IO31 ATE.UIO.IO32 ATE.UIO.IO33 ATE.UIO.IO34 ATE.UIO.IO35
net class USER_FLASH: USER_FLASH.DIN USER_FLASH.DOUT USER_FLASH.FLASH1_CS_N USER_FLASH.FLASH2_CS_N USER_FLASH.SCLK
net class USER_LEDS: USER_LEDS.LED0.BLUE USER_LEDS.LED0.GREEN USER_LEDS.LED0.RED USER_LEDS.LED1.BLUE USER_LEDS.LED1.GREEN USER_LEDS.LED1.RED USER_LEDS.LED2.BLUE USER_LEDS.LED2.GREEN USER_LEDS.LED2.RED USER_LEDS.LED3.BLUE USER_LEDS.LED3.GREEN USER_LEDS.LED3.RED USER_LEDS.LED4.BLUE USER_LEDS.LED4.GREEN USER_LEDS.LED4.RED USER_LEDS.LED5.BLUE USER_LEDS.LED5.GREEN USER_LEDS.LED5.RED USER_LEDS.LED6.BLUE USER_LEDS.LED6.GREEN USER_LEDS.LED6.RED USER_LEDS.LED7.BLUE USER_LEDS.LED7.GREEN USER_LEDS.LED7.RED
net class VGA#: ATE.VGA#.BLUE ATE.VGA#.GREEN ATE.VGA#.HSYNC ATE.VGA#.ID0 ATE.VGA#.ID1/SDA/DDC ATE.VGA#.ID2 ATE.VGA#.ID3/SCL/DDC ATE.VGA#.KEY ATE.VGA#.RED ATE.VGA#.VSYNC
net class VGA.BLUE[7..0]: VGA.BLUE0 VGA.BLUE1 VGA.BLUE2 VGA.BLUE3 VGA.BLUE4 VGA.BLUE5 VGA.BLUE6 VGA.BLUE7
net class VGA.GREEN[7..0]: VGA.GREEN0 VGA.GREEN1 VGA.GREEN2 VGA.GREEN3 VGA.GREEN4 VGA.GREEN5 VGA.GREEN6 VGA.GREEN7
net class VGA.RED[7..0]: VGA.RED0 VGA.RED1 VGA.RED2 VGA.RED3 VGA.RED4 VGA.RED5 VGA.RED6 VGA.RED7
net class VGA: ATE.VGA#.HSYNC ATE.VGA#.VSYNC VGA.BLUE0 VGA.BLUE1 VGA.BLUE2 VGA.BLUE3 VGA.BLUE4 VGA.BLUE5 VGA.BLUE6 VGA.BLUE7 VGA.GREEN0 VGA.GREEN1 VGA.GREEN2 VGA.GREEN3 VGA.GREEN4 VGA.GREEN5 VGA.GREEN6 VGA.GREEN7 VGA.RED0 VGA.RED1 VGA.RED2 VGA.RED3 VGA.RED4 VGA.RED5 VGA.RED6 VGA.RED7 VGA.VGA_CLK
net class TFT_TOUCH: TFT_TOUCH.X+ TFT_TOUCH.X- TFT_TOUCH.Y+ TFT_TOUCH.Y-
component class LCDTFT: NT42 NT43 NT44 R215 U48

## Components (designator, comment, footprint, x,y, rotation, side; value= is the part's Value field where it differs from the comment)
"Altium Logo BOT1" "Altium(2009)" LOGO-ALTIUM-NEW 4035,4446.45 r180 bottom locked
BT1 "CELLBATT 20mm HEADER" CELL_HOLDER 4215,4705 r180 top locked
C1 "220uF 10V" CAPC7343-STAR -160,5585 r270 top locked
C2 "220uF 10V" CAPC7343-STAR -160,2040 r270 top locked
C3 "10uF 20V" CAPC3528-STAR#1 -355,4080 r180 top locked
C4 "10uF 20V" CAPC3528-STAR#1 -50,1595 r180 top locked
C5 "1uF 10V" CAPC1005-STAR#1 1374.99,950 r180 bottom locked (schematic designator C13)
C6 "1uF 10V" CAPC1005-STAR#1 1175,950 r180 bottom locked (schematic designator C14)
C7 "4.7nF 10V" CAPC1005-STAR#1 -200,3906.82 r180 bottom locked (schematic designator C11)
C8 "1uF 10V" CAPC1005-STAR#1 -300,3851.36 r0 bottom locked (schematic designator C1)
C9 "1uF 10V" CAPC1005-STAR#1 -300,3685 r0 bottom locked (schematic designator C2)
C10 "1uF 10V" CAPC1005-STAR#1 -200,3795.91 r0 bottom locked (schematic designator C3)
C11 "1uF 10V" CAPC1005-STAR#1 -200,3625 r180 bottom locked (schematic designator C4)
C12 "1uF 10V" CAPC1005-STAR#1 -200,3962.27 r180 bottom locked (schematic designator C5)
C13 "4.7nF 10V" CAPC1005-STAR#1 -300,3906.82 r0 bottom locked (schematic designator C6)
C14 "1uF 10V" CAPC1005-STAR#1 -200,4073.18 r0 bottom locked (schematic designator C7)
C15 "1uF 10V" CAPC1005-STAR#1 -200,4128.64 r0 bottom locked (schematic designator C8)
C16 "1uF 10V" CAPC1005-STAR#1 -200,4184.09 r0 bottom locked (schematic designator C9)
C17 "1uF 10V" CAPC1005-STAR#1 -300,4295 r0 bottom locked (schematic designator C10)
C18 "4.7nF 10V" CAPC1005-STAR#1 -200,4239.55 r0 bottom locked (schematic designator C12)
C19 "10uF 10V" CAPC2012-STAR 110,2665 r0 bottom locked (schematic designator C1)
C20 "10uF 10V" CAPC2012-STAR -320,2665 r0 bottom locked (schematic designator C2)
C21 "100nF 16V" CAPC1005-STAR#1 -320,2745 r0 bottom locked (schematic designator C3)
C22 "100nF 16V" CAPC1005-STAR#1 110,2745 r0 bottom locked (schematic designator C4)
C23 "10uF 10V" CAPC2012-STAR 110,2525 r0 bottom locked (schematic designator C5)
C24 "100nF 16V" CAPC1005-STAR#1 110,2595 r180 bottom locked (schematic designator C6)
C25 "10uF 10V" CAPC2012-STAR 110,2385.63 r0 bottom locked (schematic designator C7)
C26 "100nF 16V" CAPC1005-STAR#1 110,2455.63 r0 bottom locked (schematic designator C8)
C27 "10uF 10V" CAPC2012-STAR -75,2525 r0 bottom locked (schematic designator C9)
C28 "220pF 50V 1005 COG" CAPC1005-STAR#1 -75,2595 r0 bottom locked (schematic designator C10)
C29 "10nF 16V" CAPC1005-STAR#1 110,2795 r180 bottom locked (schematic designator C11)
C30 "10nF 16V" CAPC1005-STAR#1 110,2895 r180 bottom locked (schematic designator C12)
C31 "10uF 10V" CAPC2012-STAR -75,2760 r0 bottom locked (schematic designator C13)
C32 "220pF 50V 1005 COG" CAPC1005-STAR#1 -75,2837.5 r0 bottom locked (schematic designator C14)
C33 "15pF 50V" CAPC1005-STAR#1 7930,3995 r0 top locked (schematic designator C1)
C34 "15pF 50V" CAPC1005-STAR#1 8045,3995 r180 top locked (schematic designator C2)
C35 "0.1uF 16V" CAPC1005-STAR#1 7926.65,3525 r180 top locked (schematic designator C4)
C36 "10uF 20V" CAPC3528-STAR#1 8125,3255 r90 top locked (schematic designator C3)
C37 "0.1uF 16V" CAPC1005-STAR#1 4078,949 r180 bottom (schematic designator C1)
C38 "0.1uF 16V" CAPC1005-STAR#1 3829,1075 r90 bottom locked (schematic designator C2)
C39 "0.1uF 16V" CAPC1005-STAR#1 7930,2510 r0 bottom locked (schematic designator C1)
C40 "10uF 20V" CAPC3528-STAR#1 2975,5205 r270 bottom locked (schematic designator C1)
C41 "0.1uF 25V" CAPC1005-STAR#1 3125,5345 r180 bottom locked (schematic designator C2)
C42 "0.1uF 25V" CAPC1005-STAR#1 3125,5120 r0 bottom locked (schematic designator C3)
C43 "0.1uF 25V" CAPC1005-STAR#1 2125,6045 r180 bottom locked (schematic designator C4)
C44 "0.1uF 25V" CAPC1005-STAR#1 2415,5730 r0 bottom locked (schematic designator C5)
C45 "22pF 50V" CAPC1005-STAR#1 2635,5680 r0 bottom locked (schematic designator C6)
C46 "22pF 50V" CAPC1005-STAR#1 2635,5380 r180 bottom locked (schematic designator C7)
C47 "0.1uF 25V" CAPC1005-STAR#1 2415,5780 r180 bottom locked (schematic designator C8)
C48 "0.1uF 25V" CAPC1005-STAR#1 2595,6045 r180 bottom locked (schematic designator C9)
C49 "10uF 20V" CAPC3528-STAR#1 2975,5585 r270 bottom locked (schematic designator C10)
C50 "0.1uF 25V" CAPC1005-STAR#1 2080,5400 r0 bottom locked (schematic designator C11)
C51 "0.1uF 25V" CAPC1005-STAR#1 2635,5265 r180 bottom locked (schematic designator C12)
C52 "0.1uF 25V" CAPC1005-STAR#1 3125,5725 r180 bottom locked (schematic designator C13)
C53 "0.1uF 25V" CAPC1005-STAR#1 3125,5500 r0 bottom locked (schematic designator C14)
C54 "0.1uF 25V" CAPC1005-STAR#1 3470,5405 r180 bottom locked (schematic designator C15)
C55 "0.1uF 16V" CAPC1005-STAR#1 8165,4610 r270 top locked (schematic designator C1)
C56 "0.1uF 16V" CAPC1005-STAR#1 8165,4475 r270 top locked (schematic designator C2)
C57 "10nF 16V" CAPC1005-STAR#1 8165,4305 r90 top locked (schematic designator C3)
C58 "10nF 16V" CAPC1005-STAR#1 7535,4605 r90 top locked (schematic designator C4)
C59 "10nF 16V" CAPC1005-STAR#1 7535,4465 r90 top locked (schematic designator C5)
C60 "0.1uF 16V" CAPC1005-STAR#1 7535,4310 r90 top locked (schematic designator C6)
C61 "10uF 20V" CAPC3528-STAR#1 3545,1125 r180 bottom locked (schematic designator C1)
C62 "10uF 20V" CAPC3528-STAR#1 2955,1125 r180 bottom locked (schematic designator C1)
C63 "0.1uF 16V" CAPC1005-STAR#1 7385,3698.78 r90 top locked (schematic designator C1)
C64 "0.1uF 16V" CAPC1005-STAR#1 7385,3839.49 r90 top locked (schematic designator C2)
C65 "0.1uF 16V" CAPC1005-STAR#1 6740,4055.15 r270 top locked (schematic designator C3)
C66 "0.1uF 16V" CAPC1005-STAR#1 6740,3839.49 r90 top locked (schematic designator C4)
C67 "10nF 16V" CAPC1005-STAR#1 6740,3698.78 r270 top locked (schematic designator C5)
C68 "10nF 16V" CAPC1005-STAR#1 6740,3474.85 r90 top locked (schematic designator C6)
C69 "10nF 16V" CAPC1005-STAR#1 7385,4055.15 r90 top locked (schematic designator C7)
C70 "10nF 16V" CAPC1005-STAR#1 7385,3474.85 r90 top locked (schematic designator C8)
C71 "0.1uF 16V" CAPC1005-STAR#1 6735,4428.59 r270 bottom locked (schematic designator C1_SM)
C72 "0.1uF 16V" CAPC1005-STAR#1 7385,4710 r90 bottom locked (schematic designator C2_SM)
C73 "10nF 16V" CAPC1005-STAR#1 6735,4850.71 r270 bottom locked (schematic designator C3_SM)
C74 "10nF 16V" CAPC1005-STAR#1 7385,4569.29 r90 bottom locked (schematic designator C4_SM)
C75 "0.1uF 16V" CAPC1005-STAR#1 6735,4569.29 r90 bottom locked (schematic designator C1_SM)
C76 "0.1uF 16V" CAPC1005-STAR#1 7385,4428.59 r270 bottom locked (schematic designator C2_SM)
C77 "10nF 16V" CAPC1005-STAR#1 6735,4710 r90 bottom locked (schematic designator C3_SM)
C78 "10nF 16V" CAPC1005-STAR#1 7385,4850.71 r90 bottom locked (schematic designator C4_SM)
C79 "0.1uF 16V" CAPC1005-STAR#1 6735,4850.71 r270 top locked (schematic designator C1)
C80 "0.1uF 16V" CAPC1005-STAR#1 6735,4710 r90 top locked (schematic designator C2)
C81 "0.1uF 16V" CAPC1005-STAR#1 7385,4428.59 r270 top locked (schematic designator C3)
C82 "0.1uF 16V" CAPC1005-STAR#1 7385,4850.71 r90 top locked (schematic designator C4)
C83 "10nF 16V" CAPC1005-STAR#1 6735,4569.29 r90 top locked (schematic designator C5)
C84 "10nF 16V" CAPC1005-STAR#1 6735,4428.59 r270 top locked (schematic designator C6)
C85 "10nF 16V" CAPC1005-STAR#1 7385,4710 r90 top locked (schematic designator C7)
C86 "10nF 16V" CAPC1005-STAR#1 7385,4569.29 r90 top locked (schematic designator C8)
C87 "4.7nF 250V" CAPM7163 442.24,1125 r270 bottom locked (schematic designator C169)
C88 "0.1uF 16V" CAPC1005-STAR#1 7470,1115 r180 bottom locked (schematic designator C2)
C89 "10uF 20V" CAPC3528-STAR#1 7390,1215 r0 bottom locked (schematic designator C6)
C90 "0.1uF 16V" CAPC1005-STAR#1 7515,495 r0 bottom locked (schematic designator C3)
C91 "0.1uF 16V" CAPC1005-STAR#1 7295,990 r180 bottom locked (schematic designator C4)
C92 "0.1uF 16V" CAPC1005-STAR#1 7400,990 r0 bottom locked (schematic designator C5)
C93 "10uF 20V" CAPC3528-STAR#1 7390,1374 r0 bottom locked (schematic designator C7)
C94 "0.1uF 16V" CAPC1005-STAR#1 7270,515 r180 bottom locked (schematic designator C8)
C95 "0.1uF 16V" CAPC1005-STAR#1 7280,1115 r0 bottom locked (schematic designator C9)
C96 "0.1uF 16V" CAPC1005-STAR#1 5060,5330 r0 bottom locked (schematic designator C1)
C97 "0.1uF 16V" CAPC1005-STAR#1 5075,5805 r180 bottom locked (schematic designator C2)
C98 "0.1uF 16V" CAPC1005-STAR#1 5420,5430 r0 bottom locked (schematic designator C3)
C99 "10uF 10V" CAPC2012-STAR 5445,5515 r180 bottom locked (schematic designator C4)
C100 "0.1uF 16V" CAPC1005-STAR#1 4900,5680 r180 bottom locked (schematic designator C5)
C101 "33nF 25V" CAPC1005-STAR#1 2405.87,5415 r0 top locked (schematic designator C1)
C102 "33nF 25V" CAPC1005-STAR#1 2550.87,5260 r180 top locked (schematic designator C2)
C103 "33nF 25V" CAPC1005-STAR#1 2405.87,5260 r0 top locked (schematic designator C3)
C104 "33nF 25V" CAPC1005-STAR#1 2550.87,5415 r180 top locked (schematic designator C4)
C105 "0.1uF 16V" CAPC1005-STAR#1 -182.03,5444.25 r0 bottom locked (schematic designator C15)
